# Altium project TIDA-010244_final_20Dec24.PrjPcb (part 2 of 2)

## Sheet TIDA-010244_USB_and_Power.SchDoc
size 431 x 279 mm; Date: Not shown in title block; ApprovedBy: Not shown in title block; CheckedBy: Not shown in title block; Author: Not shown in title block; CompanyName: Not shown in title block; Engineer: Not shown in title block; Organization: Not shown in title block; Address1: Not shown in title block; Address2: Not shown in title block; Address3: Not shown in title block; Address4: Not shown in title block; DocumentNumber: 6; Revision: Use project parameter SCH_Rev; SheetNumber: 5; SheetTotal: 9; PageSetup: Record=PageOptions¦CenterHorizontal=True¦CenterVertical=True¦PrintScale=1.00¦XCorrection=1.00¦YCorrection=1.00¦PrintKind=0¦BorderSize=5000000¦LeftOffset=0¦BottomOffset=0¦Orientation=2¦PaperLength=1000¦PaperWidth=1000¦Scale=100¦PaperSource=15¦PrintQuality=600¦MediaType=1¦DitherType=10¦PaperKind=Letter¦PrintScaleMode=1
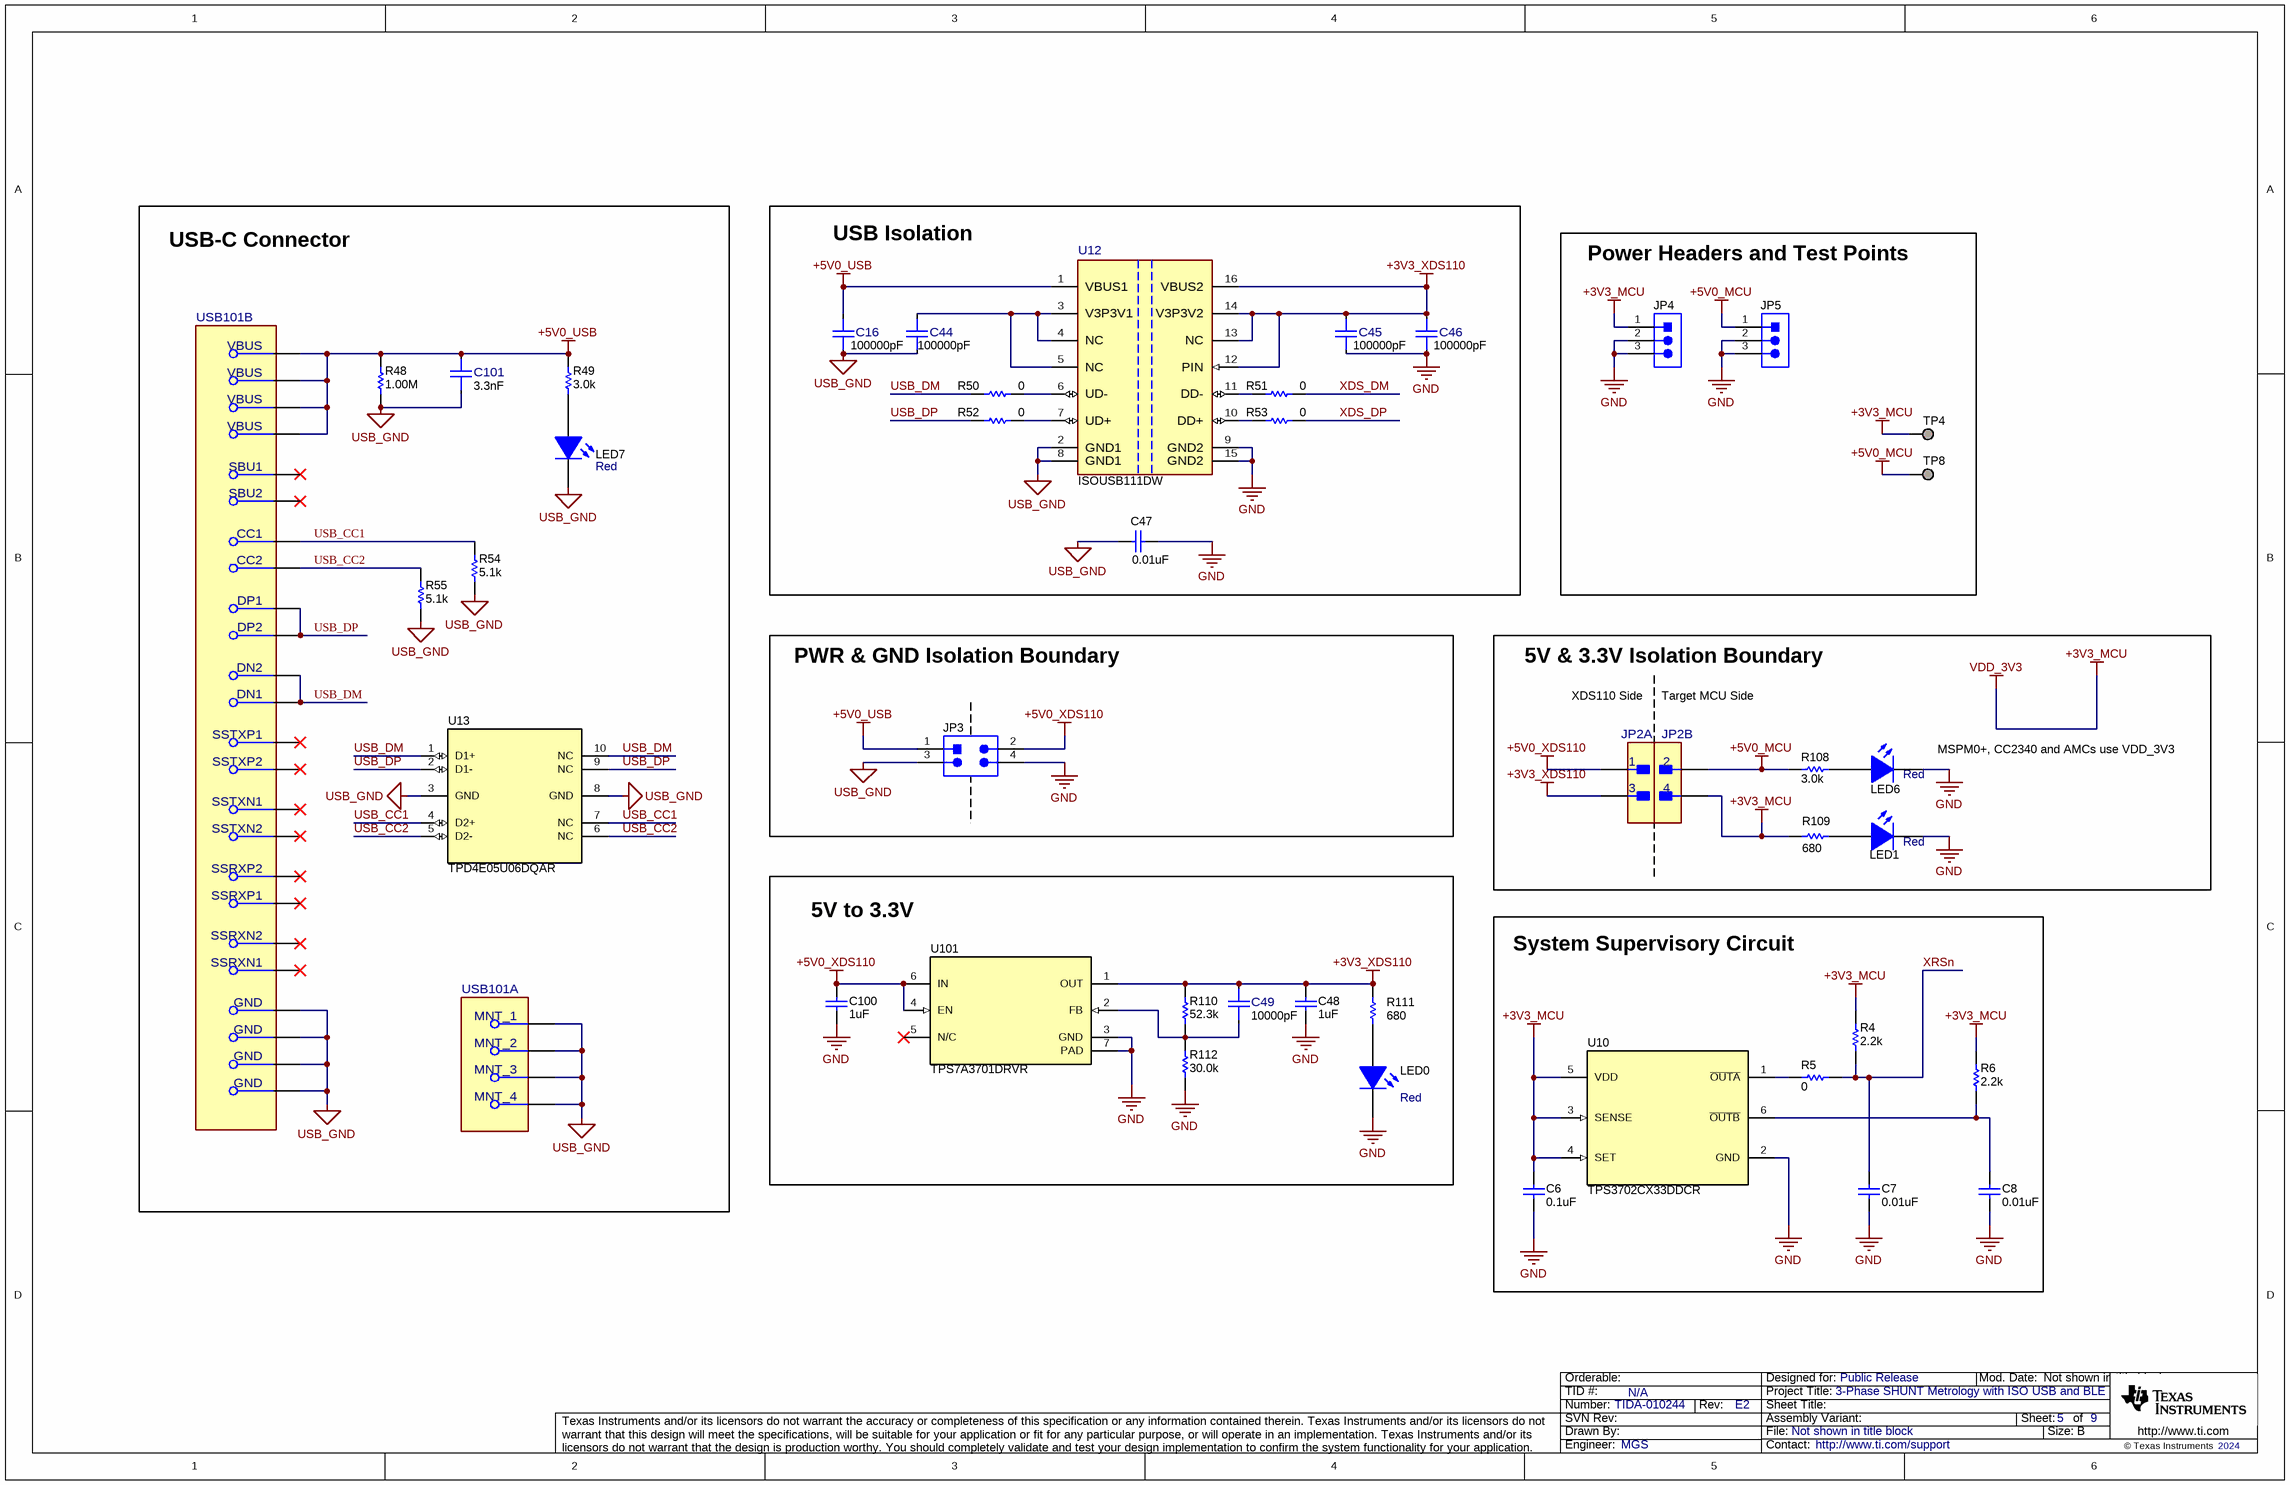
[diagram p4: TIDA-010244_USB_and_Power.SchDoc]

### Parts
C6  ValueDisplayed: 0.1uF  [0402]  (hidden comment: GRM155R71A104KA01D)
C7  ValueDisplayed: 0.01uF  [0402]  (hidden comment: GRM155R71E103KA01D)
C8  ValueDisplayed: 0.01uF  [0402]  (hidden comment: GRM155R71E103KA01D)
C16  ValueDisplayed: 100000pF  [FP-885012205018_0402-MFG]  (hidden comment: 885012205018)
C44  ValueDisplayed: 100000pF  [FP-885012205018_0402-MFG]  (hidden comment: 885012205018)
C45  ValueDisplayed: 100000pF  [FP-885012205018_0402-MFG]  (hidden comment: 885012205018)
C46  ValueDisplayed: 100000pF  [FP-885012205018_0402-MFG]  (hidden comment: 885012205018)
C47  ValueDisplayed: 0.01uF  [1812]  (hidden comment: 1812SC103KAT1A)
C48  ValueDisplayed: 1uF  [0402]  (hidden comment: 885012105012)
C49  ValueDisplayed: 10000pF  [FP-885012205050_0402-MFG]  (hidden comment: 885012205050)
C100  ValueDisplayed: 1uF  [0402]  (hidden comment: 885012105012)
C101  ValueDisplayed: 3.3nF  [FP-885012205064_0402-MFG]  (hidden comment: 885012205064)
JP2  61300421121  [FP-61300421121_HDR4-MFG]  (value not drawn)  (parts A,B of 2)
JP3  TSM-102-01-L-DV  [Samtec_TSM-102-01-x-DV]  (value not drawn)
JP4  61300311121  [WURTH_61300311121]  (value not drawn)
JP5  61300311121  [WURTH_61300311121]  (value not drawn)
LED0  value Red  [WL-SMCW_RED_0805]  (hidden comment: 150080SS75000)
LED1  value Red  [WL-SMCW_RED_0805]  (hidden comment: 150080SS75000)
LED6  value Red  [WL-SMCW_RED_0805]  (hidden comment: 150080SS75000)
LED7  value Red  [WL-SMCW_RED_0805]  (hidden comment: 150080SS75000)
R4  ValueDisplayed: 2.2k  [0402]  (hidden comment: CRCW04022K20JNED)
R5  ValueDisplayed: 0  [0402]  (hidden comment: CRCW04020000Z0ED)
R6  ValueDisplayed: 2.2k  [0603]  (hidden comment: CRCW06032K20JNEA)
R48  ValueDisplayed: 1.00M  [0402]  (hidden comment: CRCW04021M00FKED)
R49  ValueDisplayed: 3.0k  [0603]  (hidden comment: RC0603JR-073KL)
R50  ValueDisplayed: 0  [0402]  (hidden comment: RC0402JR-070RL)
R51  ValueDisplayed: 0  [0402]  (hidden comment: RC0402JR-070RL)
R52  ValueDisplayed: 0  [0402]  (hidden comment: RC0402JR-070RL)
R53  ValueDisplayed: 0  [0402]  (hidden comment: RC0402JR-070RL)
R54  ValueDisplayed: 5.1k  [0603]  (hidden comment: RC0603JR-075K1L)
R55  ValueDisplayed: 5.1k  [0603]  (hidden comment: RC0603JR-075K1L)
R108  ValueDisplayed: 3.0k  [0603]  (hidden comment: RC0603JR-073KL)
R109  ValueDisplayed: 680  [0402]  (hidden comment: CRCW0402680RJNED)
R110  ValueDisplayed: 52.3k  [0402]  (hidden comment: CRCW040252K3FKED)
R111  ValueDisplayed: 680  [0402]  (hidden comment: CRCW0402680RJNED)
R112  ValueDisplayed: 30.0k  [0402]  (hidden comment: CRCW040230K0FKED)
TP4  TESTPOINT  [TP_50MIL-25MILHOLE]  (value not drawn)  (no BOM)
TP8  TESTPOINT  [TP_50MIL-25MILHOLE]  (value not drawn)  (no BOM)
U10  TPS3702CX33DDCR  [DDC0006A_N]
U12  ISOUSB111DW  [DW0016B-MFG]
U13  TPD4E05U06DQAR  [DQA0010A]
U101  TPS7A3701DRVR  [DRV0006A]
USB101  MUP-U22001  [FP-MUP-U22001_CONN_USB_8MM94_8MM0-MFG]  (value not drawn)  (parts A,B of 2)

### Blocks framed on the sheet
USB-C Connector: C101 LED7 R48 R49 R54 R55 U13 USB101
USB Isolation: C16 C44-C47 R50-R53 U12
Power Headers and Test Points: JP4 JP5 TP4 TP8
PWR & GND Isolation Boundary: JP3
5V & 3.3V Isolation Boundary: JP2 LED1 LED6 R108 R109
5V to 3.3V: C48 C49 C100 LED0 R110-R112 U101
System Supervisory Circuit: C6-C8 R4-R6 U10

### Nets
+3V3_XDS110: C45.2 C46.2 C48.1 C49.2 JP2.3 R110.2 R111.2 U12.12(PIN) U12.13(NC) U12.14(V3P3V2) U12.16(VBUS2) U101.1(OUT)
+5V0_MCU: JP2.2 JP5.1 R108.2 TP8.1
+5V0_USB: C16.2 C101.2 JP3.1 R48.2 R49.2 U12.1(VBUS1) USB101.A4(VBUS) USB101.A9(VBUS) USB101.B4(VBUS) USB101.B9(VBUS)
+5V0_XDS110: C100.1 JP2.1 JP3.2 U101.4(EN) U101.6(IN)
GND: C6.1 C7.2 C8.2 C45.1 C46.1 C47.1 C48.2 C100.2 JP3.4 JP4.2 JP4.3 JP5.2 JP5.3 LED0.1(K) LED1.1(K) LED6.1(K) R112.1 U10.2(GND) U12.9(GND2) U12.15(GND2) U101.3(GND) U101.7(PAD)
USB_GND: C16.1 C44.1 C47.2 C101.1 JP3.3 LED7.1(K) R48.1 R54.1 R55.1 U12.2(GND1) U12.8(GND1) U13.3(GND) U13.8(GND) USB101.1(MNT_1) USB101.2(MNT_2) USB101.3(MNT_3) USB101.4(MNT_4) USB101.A1(GND) USB101.A12(GND) USB101.B1(GND) USB101.B12(GND)
VDD_3V3: C6.2 JP2.4 JP4.1 R4.2 R6.2 R109.2 TP4.1 U10.3(SENSE) U10.4(SET) U10.5(VDD)  [also labelled +3V3_MCU]
USB_CC1: R54.2 U13.4(D2+) U13.7(NC) USB101.A5(CC1)
USB_CC2: R55.2 U13.5(D2-) U13.6(NC) USB101.B5(CC2)
USB_DM: R50.1 U13.1(D1+) U13.10(NC) USB101.A7(DN1) USB101.B7(DN2)
USB_DP: R52.1 U13.2(D1-) U13.9(NC) USB101.A6(DP1) USB101.B6(DP2)
XDS_DM: R51.2
XDS_DP: R53.2
XRSn: C7.1 R4.1 R5.2
NetC8_1: C8.1 R6.1 U10.6(~{OUTB})
NetC44_2: C44.2 U12.3(V3P3V1) U12.4(NC) U12.5(NC)
NetC49_1: C49.1 R110.1 R112.2 U101.2(FB)
NetLED0_2: LED0.2(A) R111.1
NetLED1_2: LED1.2(A) R109.1
NetLED6_2: LED6.2(A) R108.1
NetLED7_2: LED7.2(A) R49.1
NetR5_1: R5.1 U10.1(~{OUTA})
NetR50_2: R50.2 U12.6(UD-)
NetR51_1: R51.1 U12.11(DD-)
NetR52_2: R52.2 U12.7(UD+)
NetR53_1: R53.1 U12.10(DD+)

Not connected (* = marked no-connect by the designer): U101 5(N/C)*; USB101 A2(SSTXP1)* A3(SSTXN1)* A8(SBU1)* A10(SSRXN2)* A11(SSRXP2)* B2(SSTXP2)* B3(SSTXN2)* B8(SBU2)* B10(SSRXN1)* B11(SSRXP1)*

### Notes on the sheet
- XDS110 Side
- Target MCU Side
- MSPM0+, CC2340 and AMCs use VDD_3V3

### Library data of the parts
C6 = CMP-0006629-2: CAP, CERM, 0.1 uF, 10 V, +/- 10%, X7R, 0402; Manufacturer: MuRata; Polarized: N; Value: 0.1uF; U/M: EA; Cap_F: 100nF; Value1: Unknown; VDC_V: 10V; TaMin_C: -55°C; TaMax_C: 125°C; SizeArea_mm2: 0.5; SizeAreaWB_mm2: 3; SizeX_mm: 1; SizeZ_mm: 0.6; AEC Category: Q200
C7 C8 = CMP-0006658-2: CAP, CERM, 0.01 uF, 25 V, +/- 10%, X7R, 0402; Manufacturer: MuRata; Polarized: N; Value: 0.01uF; U/M: EA; Cap_F: 10nF; Value1: Unknown; VDC_V: 25V; TaMin_C: -55°C; TaMax_C: 125°C; SizeArea_mm2: 0.5; SizeAreaWB_mm2: 3; SizeX_mm: 1; SizeZ_mm: 0.6; AEC Category: Q200
C16 C44-C46 = CMP-0090362-1: 0.1µF ±10% 10V Ceramic Capacitor X7R 0402 (1005 Metric); Manufacturer: Wurth Electronics; AEC Qualified: No; Value: 100nF; SizeZ_mm: 0.55mm; TempCo: 15%
C47 = CMP-0009297-2: CAP, CERM, 0.01 uF, 1500 V, +/- 10%, X7R, 1812; Manufacturer: AVX; TaMin_C: -55°C; ESR_ohm: 0.05; Polarized: N; SizeAreaWB_mm2: 23.1; Value1: 0.05 ohm; U/M: EA; Value: 0.01uF; TaMax_C: 125°C; SizeZ_mm: 1.35; SizeX_mm: 4.5; SizeY_mm: 3.2; Value2: 1500V; SizeArea_mm2: 14.4; Cap_F: 10nF; VDC_V: 1.5kV; AEC Category: Q200
C48 C100 = CMP-0064924-2: CAP, CERM, 1 uF, 10 V,+/- 20%, X5R, 0402; Manufacturer: Wurth Elektronik; Polarized: N; Value: 1uF; U/M: EA; Cap_F: 1µF; Value1: Unknown; VDC_V: 10V; TaMin_C: -55°C; TaMax_C: 85°C; SizeArea_mm2: 0.5; SizeAreaWB_mm2: 3; SizeX_mm: 1; SizeZ_mm: 0.6; AEC Category: Q200
C49 = CMP-0090363-1: 10000pF ±10% 25V Ceramic Capacitor X7R 0402 (1005 Metric); Manufacturer: Wurth Electronics; SizeZ_mm: 0.55mm; Cap_F: 10nF; AEC Qualified: No; Value: 10nF; TempCo: 15%
C101 = CMP-0092424-1: Cap Cer 3300pF 50V X7R 0402; Manufacturer: Wurth Electronics; TempCo: 15%; AEC Qualified: No; Value: 3.3nF; SizeZ_mm: 0.55mm; Tolerance_%: 10%
JP2 = CMP-0092422-1: THT Vertical Pin Header WR-PHD, Pitch 2.54 mm, Dual Row, 4 pins; Manufacturer: Wurth Electronics; DUT-Pitch_mm: 2.54mm; SizeZ_mm: 8.89mm; Voltage_V: 250V; Conn Gender: Male; AEC Qualified: No; Row_Count: 2; ContactFinish: Gold; Conn Orientation: Straight; Current_A: 3A
JP3 = CMP-0055559-1: Header, 2.54mm, 2x2, Gold, SMT; Manufacturer: Samtec; CNHeader: TRUE; Shrouded: N; Gender: Male; Cert_CSA: Y; Voltage_V: 475V; Row_Count: 2; Pitch_mm: 2.54; CT: FALSE
JP4 JP5 = CMP-0054796-1: Header, 2.54 mm, 3x1, Gold, TH; Manufacturer: Wurth Elektronik; Green_Lifecycle: Active; Green_REACh: Passed; CNHeader: TRUE; CT: FALSE
LED0 LED1 LED6 LED7 = CMP-0002951-3: LED, Red, SMD; Manufacturer: Wurth Elektronik; Type: AlInGaP; Vf_V: 1.9V; Io_A: 30mA; Vr_V: 5V; Ir_A: 25µA; Tjmax_C: 85°C; Power_TotalModule: 72mW; Value1: 0.072W; Angle: 140
R4 = CMP-0026890-5: RES, 2.2 k, 5%, 0.063 W, AEC-Q200 Grade 0, 0402; Manufacturer: Vishay-Dale; Value: 2.2k; Value_Code: 2k20; Power_W: 63mW; Value2: 0.063W; VDC_V: 50V; TempCo: 200 ppm/C; SizeArea_mm2: 0.5; SizeX_mm: 1; SizeZ_mm: 0.6; EIA_Code: E24; AEC Category: Q200; AEC Qualified: Y; AEC Grade: 0
R5 = CMP-0026822-3: RES, 0, 5%, 0.063 W, AEC-Q200 Grade 0, 0402; Manufacturer: Vishay-Dale; Value: 0; Value_Code: 0000; Power_W: 63mW; Value2: 0.063W; VDC_V: 50V; TempCo: 200 ppm/C; SizeArea_mm2: 0.5; SizeX_mm: 1; SizeZ_mm: 0.6; EIA_Code: E24; AEC Category: Q200; AEC Qualified: Y
R6 = CMP-0025769-4: RES, 2.2 k, 5%, 0.1 W, AEC-Q200 Grade 0, 0603; Manufacturer: Vishay-Dale; Value: 2.2k; Value_Code: 2k20; Power_W: 100mW; Value2: 0.1W; VDC_V: 75V; TempCo: 200 ppm/C; SizeArea_mm2: 1.28; SizeX_mm: 1.6; SizeY_mm: 0.8; SizeZ_mm: 1; EIA_Code: E24; AEC Category: Q200; AEC Qualified: Y; AEC Grade: 0
R48 = CMP-0026100-2: RES, 1.00 M, 1%, 0.063 W, AEC-Q200 Grade 0, 0402; Manufacturer: Vishay-Dale; Value: 1.00Meg; Res_ohm: 1M; Value_Code: 1M00; Power_W: 63mW; Value2: 0.063W; VDC_V: 50V; TempCo: 100 ppm/C; SizeArea_mm2: 0.5; SizeX_mm: 1; SizeZ_mm: 0.6; EIA_Code: E96; AEC Category: Q200; AEC Qualified: Y; AEC Grade: 0
R49 R108 = CMP-0025921-5: RES, 3.0 k, 5%, 0.1 W, 0603; Manufacturer: Yageo; Power_W: 100mW; TempCo: 100 ppm/C; Value_Code: 3k00; Value: 3.0k; EIA_Code: E24; Res_ohm: 3k; SizeX_mm: 1.6; SizeY_mm: 0.8; SizeZ_mm: 1; Value2: 0.1W; SizeArea_mm2: 1.28; AEC Qualified: N; VDC_V: 75V; AEC Category: Q200; SizeAreaWB_mm2: 4.68
R50-R53 = CMP-0027004-2: RES, 0, 5%, 0.063 W, 0402; Manufacturer: Yageo America; Power_W: 63mW; TempCo: 200 ppm/C; Value_Code: 0000; U/M: EA; Value: 0; EIA_Code: E24; SizeX_mm: 1; SizeY_mm: 0.5; SizeZ_mm: 0.6; Value2: 0.063W; VDC_V: 50V; AEC Category: Q200
R54 R55 = CMP-0025932-5: RES, 5.1 k, 5%, 0.1 W, 0603; Manufacturer: Yageo; Power_W: 100mW; TempCo: 100 ppm/C; Value_Code: 5k10; Value: 5.1k; EIA_Code: E24; SizeX_mm: 1.6; SizeY_mm: 0.8; SizeZ_mm: 1; Value2: 0.1W; SizeArea_mm2: 1.28; AEC Qualified: N; VDC_V: 75V; AEC Category: Q200; SizeAreaWB_mm2: 4.68
R109 R111 = CMP-0026962-3: RES, 680, 5%, 0.063 W, AEC-Q200 Grade 0, 0402; Manufacturer: Vishay-Dale; Power_W: 63mW; TempCo: 200 ppm/C; Value_Code: 680R; Value: 680; EIA_Code: E24; SizeX_mm: 1; SizeY_mm: 0.5; SizeZ_mm: 0.6; Value2: 0.063W; AEC Qualified: Y; VDC_V: 50V; AEC Category: Q200; AEC Grade: 0
R110 = CMP-0026441-2: RES, 52.3 k, 1%, 0.063 W, AEC-Q200 Grade 0, 0402; Manufacturer: Vishay-Dale; Power_W: 63mW; TempCo: 100 ppm/C; Value_Code: 52k3; Value: 52.3k; EIA_Code: E96; SizeX_mm: 1; SizeY_mm: 0.5; SizeZ_mm: 0.6; Value2: 0.063W; AEC Qualified: Y; VDC_V: 50V; AEC Category: Q200; AEC Grade: 0
R112 = CMP-0078244-2: RES, 30.0 k, 1%, 0.063 W, AEC-Q200 Grade 0, 0402; Manufacturer: Vishay-Dale; Power_W: 63mW; Green_Lifecycle: Active; TempCo: 100 ppm/C; Value_Code: 30k0; Green_REACh: Passed; Value: 30.0k; Res_ohm: 30k; SizeX_mm: 1; SizeY_mm: 0.5; SizeZ_mm: 0.6; Value2: 0.063W; AEC Qualified: Y; VDC_V: 50V; AEC Grade: 0; AEC Category: Q200
TP4 TP8 = CMP-0078143-3: TEST POINT.  No entry in BOM.
U10 = CMP-0067340-2: High-Accuracy, Fixed-Threshold OV/UV Monitor, DDC0006A (SOT-23-T-6); Alternate PartNumber: TPS3702CX33DDCT; Manufacturer: Texas Instruments; SizeArea_mm2: 4.8675; SizeAreaWB_mm2: 10.4675; SizeX_mm: 1.65; SizeY_mm: 2.95; SizeZ_mm: 0.87; CompType: IC; U/M: EA
U12 = CMP-0091303-1: Full/Low Speed Isolated USB Repeater, SOIC16-Wide; Manufacturer: Texas Instruments; Number Of Ports: 1; Usb Standard: USB 2.0; Min Supply Voltage: 3V; Data Rate: 12Mbits/s; Max Supply Voltage: 5.5V; TaMin_C: -40°C; SizeZ_mm: 2.65mm; TaMax_C: +125°C; Nominal Supply Current: 9-9.5mA; TJmax_C: +150°C; Standoff Height: 0.1mm; AEC Qualified: No
U13 = CMP-0073613-3: 4-Channel Ultra-Low-Capacitance IEC ESD Protection Diode, DQA0010A (USON-10); Alternate Manufacturer: Texas Instruments; Green_Lifecycle: Active; SizeAreaWB_mm2: 7.0; Green_REACh: Passed; SizeZ_mm: 0.55; SizeX_mm: 1.0; SizeY_mm: 2.5; CompType: IC; AEC Category: Q200; AEC Qualified: N
U101 = CMP-0066914-5: 1% High-Accuracy, 1-A, Low-Dropout Regulator with Reverse Current Protection, DRV0006A (WSON-6); Manufacturer: Texas Instruments; Alternate PartNumber: TPS7A3701DRVT; SizeX_mm: 2; CompType: IC; SizeZ_mm: 0.8; SizeArea_mm2: 4; SizeAreaWB_mm2: 9; U/M: EA
USB101 = CMP-0092137-1: Connector, USB Type-C 24 pin Mid Mount dual row Receptacle Surface Mount; Manufacturer: MUP; ContactFinish: Gold,Nickel; Usb Standard: OTHER; AEC Qualified: No; Conn Orientation: Horizontal; Shrouded: true; SizeZ_mm: 2.81mm; Is Female: yes; DUT-Pitch_mm: 0.5mm

## Sheet TIDA-010244_BLE_Wireless.SchDoc
size A4; Date: Not shown in title block; ApprovedBy: Not shown in title block; CheckedBy: Not shown in title block; Author: Not shown in title block; CompanyName: Not shown in title block; Engineer: Not shown in title block; Organization: Not shown in title block; Address1: Not shown in title block; Address2: Not shown in title block; Address3: Not shown in title block; Address4: Not shown in title block; DocumentNumber: 1; Revision: Use project parameter SCH_Rev; SheetNumber: 2; SheetTotal: 9; PageSetup: Record=PageOptions¦CenterHorizontal=True¦CenterVertical=True¦PrintScale=0.69¦XCorrection=1.00¦YCorrection=1.00¦PrintKind=0¦BorderSize=5000000¦LeftOffset=0¦BottomOffset=0¦Orientation=2¦PaperLength=1000¦PaperWidth=1000¦Scale=100¦PaperSource=15¦PrintQuality=600¦MediaType=1¦DitherType=10¦PaperKind=Letter¦PrintScaleMode=1
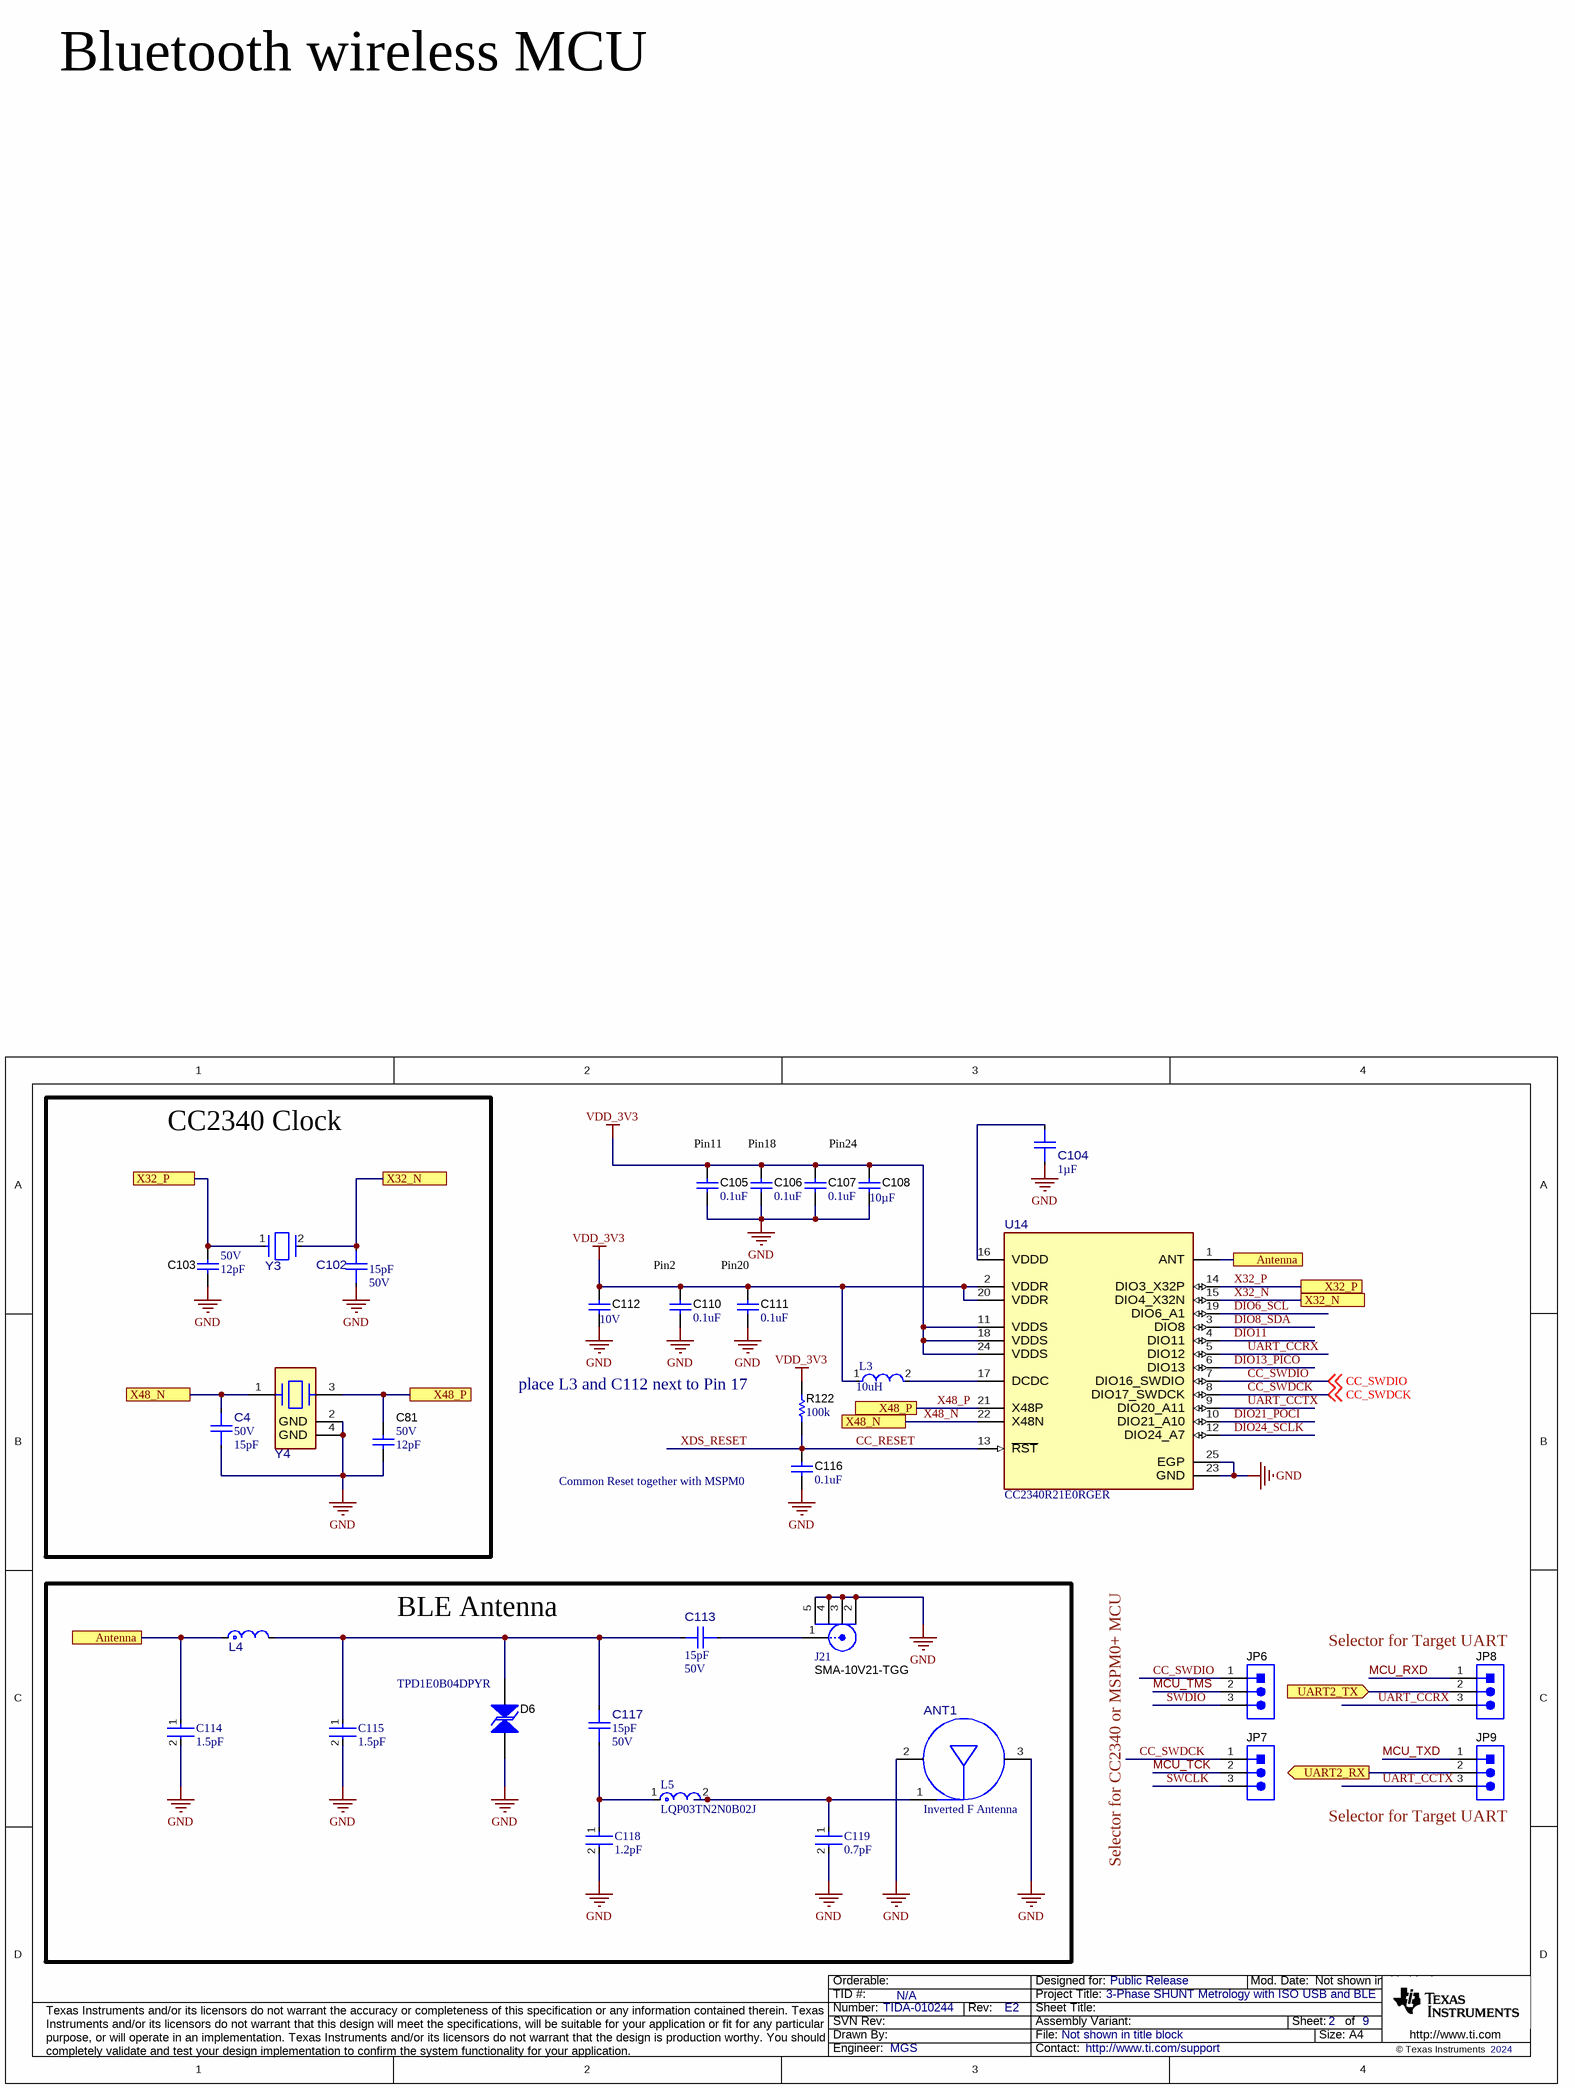
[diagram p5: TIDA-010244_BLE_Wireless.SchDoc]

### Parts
ANT1  Inverted F Antenna  [0-MFG]
C4  VDC_V: 50V  ValueDisplayed: 15pF  [FP-GRM0335C1H150GA01D_0201-IPC_B]  (hidden comment: GRM0335C1H150GA01D)
C81  VDC_V: 50V  ValueDisplayed: 12pF  [0201]  (hidden comment: GRM0335C1H120JA01D)
C102  ValueDisplayed: 15pF  VDC_V: 50V  [FP-GRM0335C1H150GA01D_0201-IPC_B]  (hidden comment: GRM0335C1H150GA01D)
C103  VDC_V: 50V  ValueDisplayed: 12pF  [0201]  (hidden comment: GRM0335C1H120JA01D)
C104  Cap_F: 1µF  [FP-GRM155Z71A105KE01D_0402-MFG]  (hidden comment: GRM155Z71A105KE01D)
C105  value 0.1uF  [0201]  (hidden comment: GRM033C71A104KE14D)
C106  value 0.1uF  [0201]  (hidden comment: GRM033C71A104KE14D)
C107  value 0.1uF  [0201]  (hidden comment: GRM033C71A104KE14D)
C108  Cap_F: 10µF  [0603]  (hidden comment: GRM188Z71A106KA73D)
C110  value 0.1uF  [0201]  (hidden comment: GRM033C71A104KE14D)
C111  value 0.1uF  [0201]  (hidden comment: GRM033C71A104KE14D)
C112  VDC_V: 10V  [0603]  (hidden comment: GRM188Z71A106KA73D)
C113  ValueDisplayed: 15pF  VDC_V: 50V  [FP-885012005056_0402-MFG]  (hidden comment: 885012005056)
C114  1.5pF  [FP-GRM033-0_03-IPC_C]
C115  1.5pF  [FP-GRM033-0_03-IPC_C]
C116  value 0.1uF  [0201]  (hidden comment: GRM033C71A104KE14D)
C117  ValueDisplayed: 15pF  VDC_V: 50V  [FP-885012005056_0402-MFG]  (hidden comment: 885012005056)
C118  1.2pF  [FP-GRM033-0_03-IPC_C]
C119  0.7pF  [FP-GRM033-0_03-MFG]
D6  TPD1E0B04DPYR  [DPY0002A]
J21  SMA-10V21-TGG  [Hustsan_SMA-10V21-TGG]
JP6  61300311121  [WURTH_61300311121]  (value not drawn)
JP7  61300311121  [WURTH_61300311121]  (value not drawn)
JP8  61300311121  [WURTH_61300311121]  (value not drawn)
JP9  61300311121  [WURTH_61300311121]  (value not drawn)
L3  10uH  [FP-LQM18DN_70-IPC_B]
L4  LQP03TN2N8B02J  [FP-LQP03TN2N8B02J_0201 (0603)-MFG]  (value not drawn)
L5  LQP03TN2N0B02J  [FP-LQP03TG_02-IPC_B]
R122  ValueDisplayed: 100k  [0201]  (hidden comment: RC0201FR-7D100KL)
U14  CC2340R21E0RGER  [RGE0024B-MFG]
Y3  TZ3359DAAO73  [FP-TZ3359DAAO73_SMT2_1MM65_1MM05-MFG]  (value not drawn)
Y4  TZ3908AAAO43  [FP-TZ3908AAAO43_SMT4_2MM05_1MM65-MFG]  (value not drawn)

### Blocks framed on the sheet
CC2340 Clock: C4 C81 C102 C103 Y3 Y4
BLE Antenna: ANT1 C113-C115 C117-C119 D6 J21 L4 L5

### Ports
Antenna, UART2_RX (out), UART2_TX (in), X32_N, X32_P, X48_N, X48_P

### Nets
GND: ANT1.2(GND) ANT1.3(GND) C4.1 C81.2 C102.1 C103.2 C104.1 C105.1 C106.1 C107.1 C108.1 C110.1 C111.1 C112.2 C114.2 C115.2 C116.1 C118.2 C119.2 D6.1 J21.2 J21.3 J21.4 J21.5 U14.23(GND) U14.25(EGP) Y4.2(GND) Y4.4(GND)
VDD_3V3: C105.2 C106.2 C107.2 C108.2 C110.2 C111.2 C112.1 L3.1 R122.1 U14.2(VDDR) U14.11(VDDS) U14.18(VDDS) U14.20(VDDR) U14.24(VDDS)
Antenna: C114.1 L4.1 U14.1(ANT) ; port Antenna
CC_RESET: C116.2 R122.2 U14.13(~{RST})  [also labelled XDS_RESET]
CC_SWDCK: JP7.1 U14.8(DIO17_SWDCK) ; off-sheet CC_SWDCK
CC_SWDIO: JP6.1 U14.7(DIO16_SWDIO) ; off-sheet CC_SWDIO
DIO6_SCL: U14.19(DIO6_A1)
DIO8_SDA: U14.3(DIO8)
DIO11: U14.4(DIO11)
DIO13_PICO: U14.6(DIO13)
DIO21_POCI: U14.10(DIO21_A10)
DIO24_SCLK: U14.12(DIO24_A7)
MCU_RXD: JP8.1
MCU_TCK: JP7.2
MCU_TMS: JP6.2
MCU_TXD: JP9.1
SWCLK: JP7.3
SWDIO: JP6.3
UART_CCRX: JP8.3 U14.5(DIO12)  [project net HY_RX]
UART_CCTX: JP9.3 U14.9(DIO20_A11)  [project net HY_TX]
UART_RX_to_BLE: JP9.2 ; port UART2_RX
UART_TX_to_BLE: JP8.2 ; port UART2_TX
X32_N: C102.2 U14.15(DIO4_X32N) Y3.2 ; port X32_N
X32_P: C103.1 U14.14(DIO3_X32P) Y3.1 ; port X32_P
X48_N: C4.2 U14.22(X48N) Y4.1(1_IN/OUT) ; port X48_N
X48_P: C81.1 U14.21(X48P) Y4.3(2_IN/OUT) ; port X48_P
NetANT1_1: ANT1.1(Feed) C119.1 L5.2
NetC104_2: C104.2 U14.16(VDDD)
NetC113_1: C113.1 J21.1
NetC113_2: C113.2 C115.1 C117.2 D6.2 L4.2
NetC117_1: C117.1 C118.1 L5.1
NetL3_2: L3.2 U14.17(DCDC)

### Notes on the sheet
- Bluetooth wireless MCU
- (near C105) Pin11
- (near C106) Pin18
- Pin24
- (near C110) Pin2
- (near C111) Pin20
- (near R122) place L3 and C112 next to Pin 17
- Common Reset together with MSPM0
- (near JP8) Selector for Target UART
- (near JP9) Selector for Target UART
- Selector for CC2340 or MSPM0+ MCU

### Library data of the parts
ANT1 = CMP-0091830-1: 2.4-GHz Inverted F Antenna; Manufacturer: Texas Instruments; AEC Qualified: No; Number Of Bands: 1
C4 = CMP-0001348-1: Chip Multilayer Ceramic Capacitors for General Purpose, 0201, 15pF, C0G, 30ppm/°C, 2%, 50V; Manufacturer: Murata; SizeZ_mm: 0.33mm; AEC Qualified: No
C81 C103 = CMP-0009664-3: CAP, CERM, 12 pF, 50 V, +/- 5%, C0G/NP0, 0201; Manufacturer: MuRata; SizeZ_mm: 0.26; Value: 12pF; AEC Qualified: N; TaMin_C: -55°C; SizeAreaWB_mm2: 2.08; Value1: Unknown; U/M: EA; TaMax_C: 125°C; SizeY_mm: 0.3; SizeArea_mm2: 0.18; SizeX_mm: 0.6; AEC Category: Q200
C102 = CMP-0001348-1: Chip Multilayer Ceramic Capacitors for General Purpose, 0201, 15pF, C0G, 30ppm/°C, 2%, 50V; Manufacturer: Murata; AEC Qualified: No; SizeZ_mm: 0.33mm
C104 = CMP-0092999-1: Chip Multilayer Ceramic Capacitors for General Purpose, 0402, 1.0uF, X7R, 15%, 10%, 10V; Manufacturer: Murata; Value: 1µF; SizeZ_mm: 0.6mm; AEC Qualified: No
C105-C107 C110 C111 C116 = CMP-0064969-1: CAP, CERM, 0.1 uF, 10 V,+/- 10%, X7S, 0201; Manufacturer: MuRata; TaMin_C: -55°C; Polarized: N; SizeAreaWB_mm2: 2.08; Value1: Unknown; U/M: EA; TaMax_C: 125°C; SizeZ_mm: 0.26; SizeX_mm: 0.6; SizeY_mm: 0.3; Value2: 10V; SizeArea_mm2: 0.18; AEC Category: Q200; Cap_F: 100nF
C108 = CMP-0087107-2: Chip Multilayer Ceramic Capacitors for General Purpose; Manufacturer: Murata; TempCo: 15%; Tolerance_%: 10%; SizeZ_mm: 1mm; AEC Qualified: No; VDC_V: 10V
C112 = CMP-0087107-2: Chip Multilayer Ceramic Capacitors for General Purpose; Manufacturer: Murata; TempCo: 15%; Tolerance_%: 10%; SizeZ_mm: 1mm; AEC Qualified: No; Cap_F: 10µF
C113 C117 = CMP-0090358-1: 15pF ±5% 50V Ceramic Capacitor C0G, NP0 0402 (1005 Metric); Manufacturer: Wurth Electronics; AEC Qualified: No; SizeZ_mm: 0.55mm; TempCo: 30ppm/°C
C114 C115 = CMP-06035-002174-1: Chip Multilayer Ceramic Capacitors for General Purpose, 0201, 1.5pF, C0G, 30ppm/°C, 0.1pF, 50V
C118 = CMP-2010-01514-2: Chip Multilayer Ceramic Capacitors for General Purpose, 0201, 1.2pF, C0G, 30ppm/°C, 0.1pF, 50V
C119 = CMP-06035-002085-1: Chip Multilayer Ceramic Capacitors for General Purpose, 0201, 0.70pF, C0G, 30ppm/°C, 0.1pF, 50V
D6 = CMP-0073606-3: 1-Channel ESD Protection Diode for USB Type-C and Antenna Protection, DPY0002A (X1SON-2); Manufacturer: Texas Instruments; Alternate PartNumber: TPD1E0B04DPYT; CompType: IC; SizeX_mm: 1.0; SizeAreaWB_mm2: 3.2; AEC Category: Q200; SizeZ_mm: 0.45; Rating: Catalog; SizeArea_mm2: 0.6
J21 = CMP-0055832-1: Connector, SMA, Vertical, Gold, SMT; Manufacturer: Hus-Tsan Group Co., Ltd.; CT: TRUE; CNHeader: FALSE
JP6-JP9 = CMP-0054796-1: as JP4 on sheet TIDA-010244_USB_and_Power
L3 = CMP-06042-017052-1: Multilayer type Inductor for Power Lines 10uH ±20% @1MHz, 300mA, Max DCR 1.365Ω, SRF 32MHz
L4 = CMP-0001349-1: Film type RF Inductor 2.8nH ±0.1nH 500mA 0.2Ω 0201 (0603); Manufacturer: Murata; AEC Qualified: No; DCR_ohm: 0.2; SizeZ_mm: 0.33mm; Q Factor: 14; Self Resonant Frequency: 9.5GHz; Test Frequency: 500MHz
L5 = CMP-06042-009700-1: Film type RF Inductor 2nH ±0.1nH 600mA 0.15Ω 0201 (0603)
R122 = CMP-0027943-1: RES, 100 k, 1%, 0.05 W, 0201; Manufacturer: Yageo America; Power_W: 50mW; TempCo: 200 ppm/C; Value: 100k; EIA_Code: E96; SizeX_mm: 0.6; SizeY_mm: 0.3; SizeZ_mm: 0.26; Value2: 0.05W; SizeArea_mm2: 0.18; AEC Qualified: N; VDC_V: 25V; AEC Category: Q200; U/M: EA
U14 = CMP-0033813-1: SimpleLink™ Bluetooth ® 5.3 Low Energy Wireless MCU QFN24 48MHz Arm® Cortex®-M0+ 28KB RAM 256KB FLASH; Manufacturer: Texas Instruments; SizeZ_mm: 1mm; AEC Qualified: No; Core Architecture: ARM Cortex-M0+; Data Bus Width: 32bits; Interface: I2C,SPI,UART,IrDA; Max Supply Voltage: 3.8V; Memory Size: 256KBytes; Min Supply Voltage: 1.71V; Number Of A/D Converters: 1; Number Of Adc Channels: 4; Number Of I/Os: 12; Number Of Pwm Channels: 2; Ram Size: 28KBytes; Standoff Height: 0mm; TaMax_C: +125°C; TaMin_C: -40°C
Y3 = CMP-0001358-1: Crystal Unit 1.6x1.0 Tuning Fork 32.768KHz; Manufacturer: TAI-SAW Technology; Frequency Stability: 380ppm; SizeZ_mm: 0.5mm; AEC Qualified: No; Frequency Tolerance: 20ppm; Load Capacitance: 7pF; Esr: 120k
Y4 = CMP-0001392-1: Crystal Unit SMD 2.0x1.6 48.0MHz; Manufacturer: TAI-SAW Thechnology; Frequency Stability: 30ppm; Frequency_Fixed: 48MHz; SizeZ_mm: 0.5mm; AEC Qualified: No; Frequency Tolerance: 5ppm; Load Capacitance: 7pF; Esr: 30

## Sheet TIDA-010244_XDS110_MCU.SchDoc
size 431 x 279 mm; Date: Not shown in title block; ApprovedBy: Not shown in title block; CheckedBy: Not shown in title block; Author: Not shown in title block; CompanyName: Not shown in title block; Engineer: Not shown in title block; Organization: Not shown in title block; Address1: Not shown in title block; Address2: Not shown in title block; Address3: Not shown in title block; Address4: Not shown in title block; DocumentNumber: 7; Revision: Use project parameter SCH_Rev; SheetNumber: 7; SheetTotal: 9; PageSetup: Record=PageOptions¦CenterHorizontal=True¦CenterVertical=True¦PrintScale=1.00¦XCorrection=1.00¦YCorrection=1.00¦PrintKind=0¦BorderSize=5000000¦LeftOffset=0¦BottomOffset=0¦Orientation=2¦PaperLength=1000¦PaperWidth=1000¦Scale=100¦PaperSource=15¦PrintQuality=600¦MediaType=1¦DitherType=10¦PaperKind=Letter¦PrintScaleMode=1
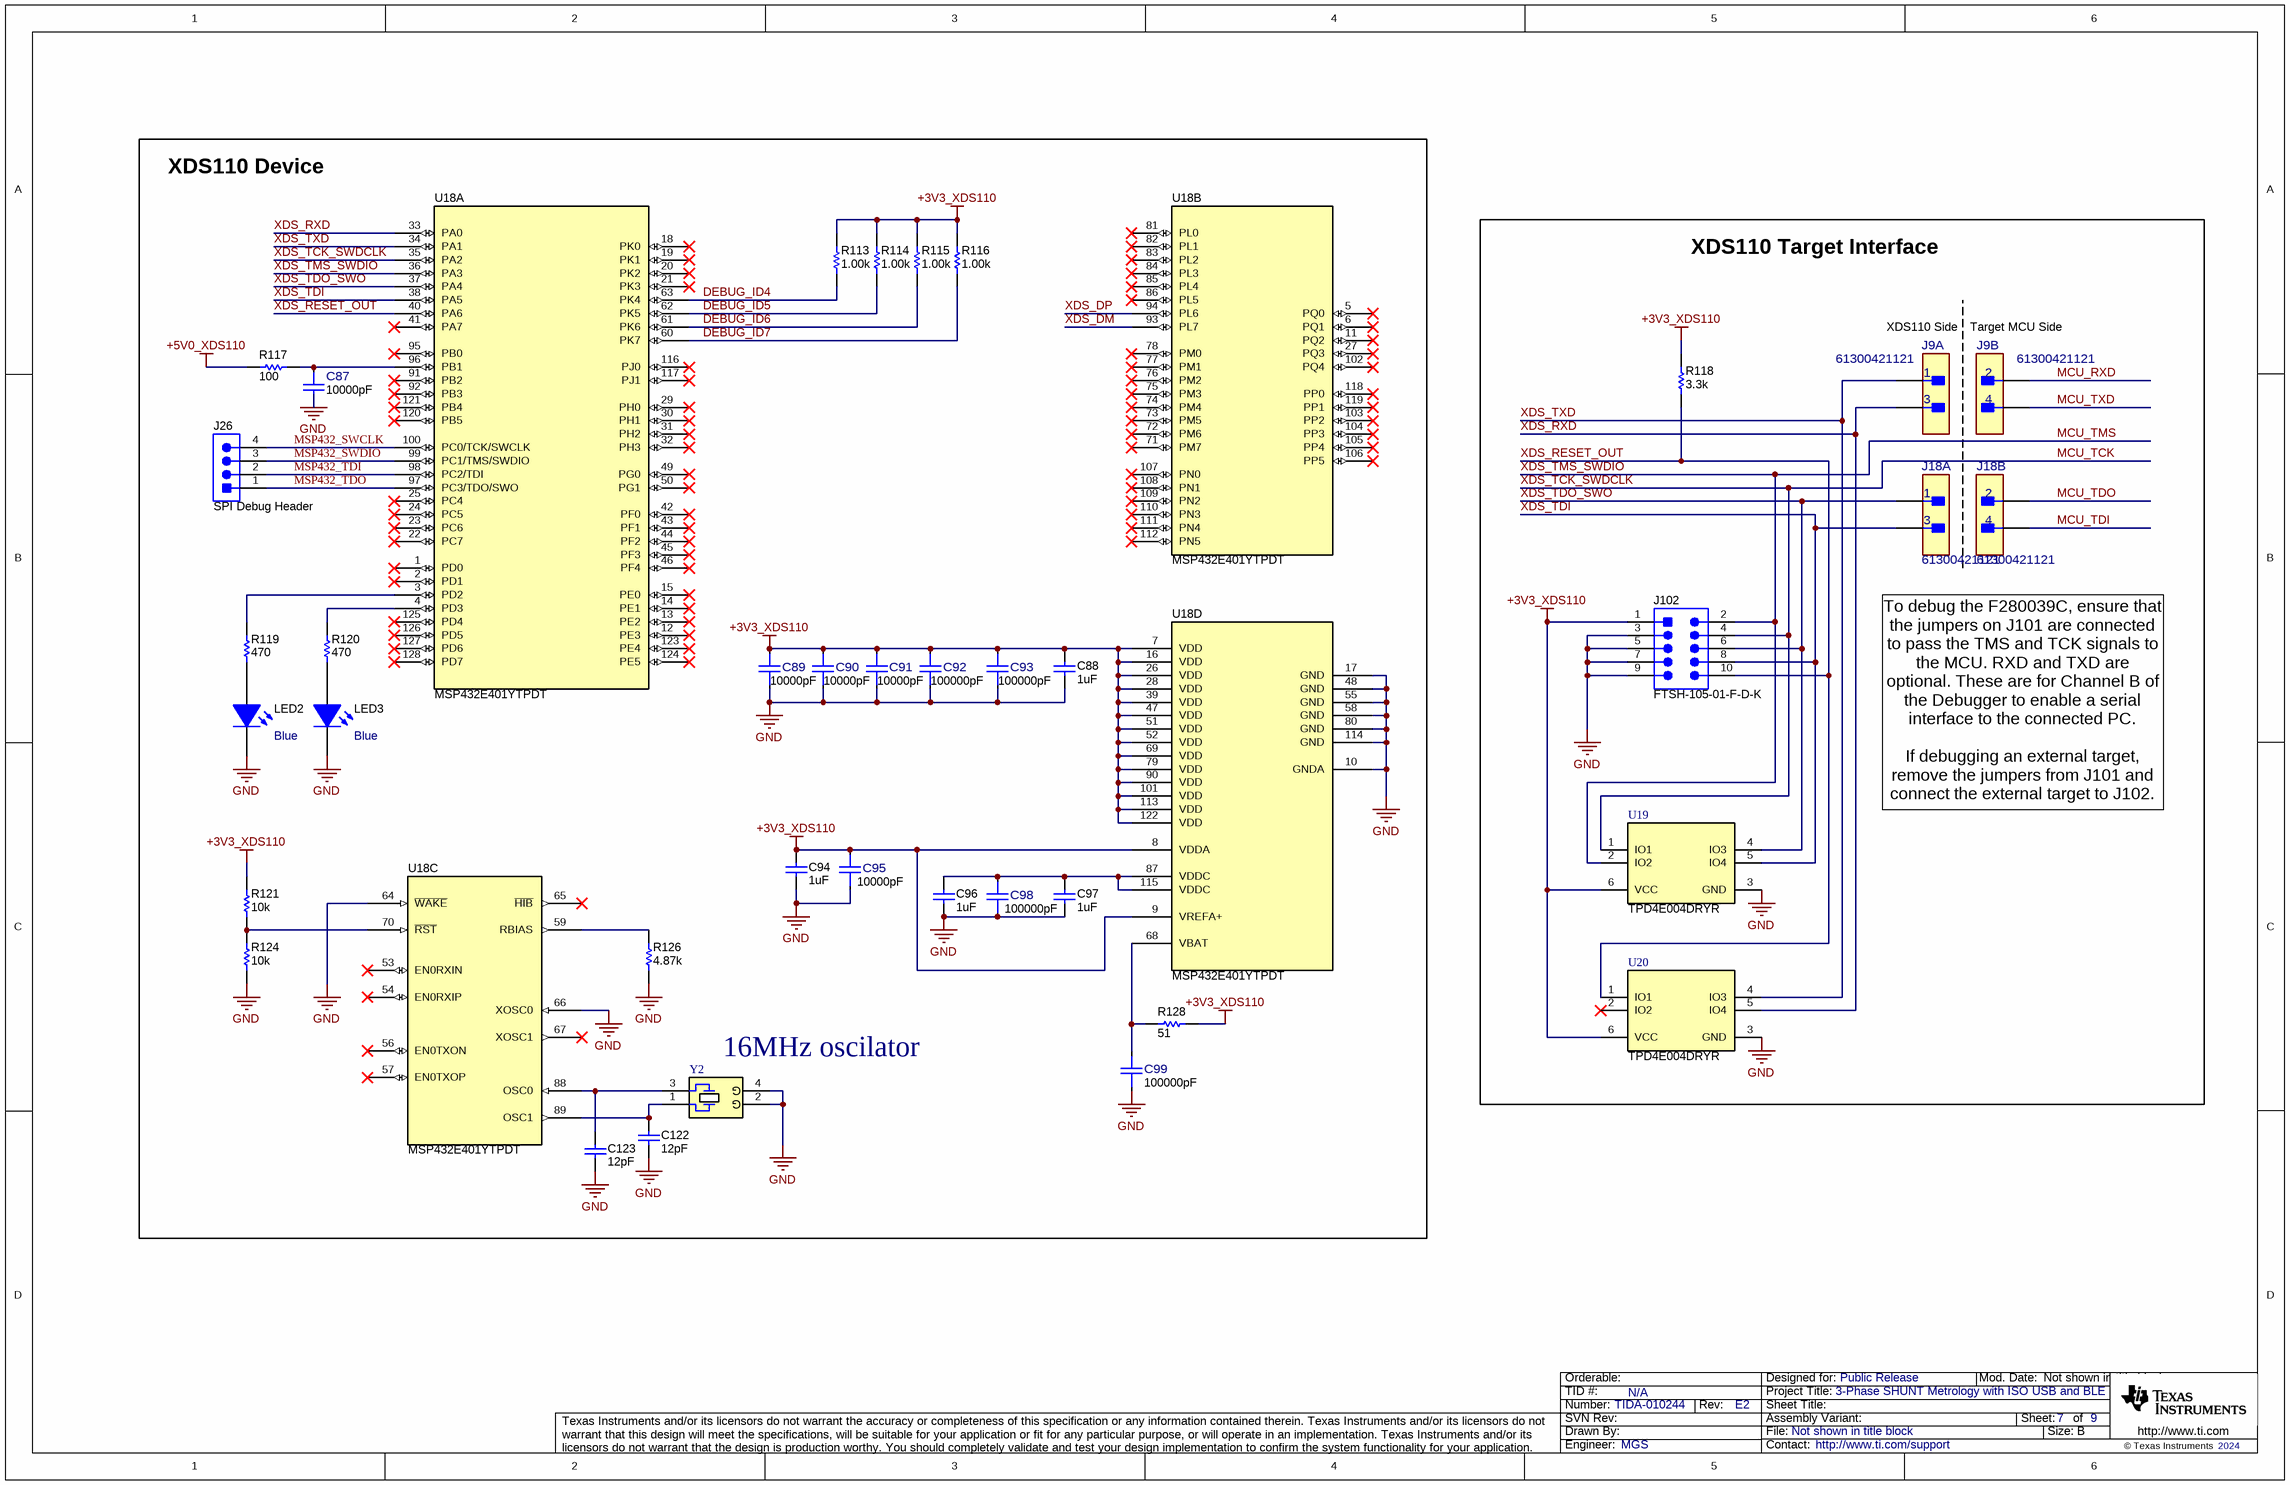
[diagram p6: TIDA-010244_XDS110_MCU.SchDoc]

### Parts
C87  ValueDisplayed: 10000pF  [FP-885012205050_0402-MFG]  (hidden comment: 885012205050)
C88  ValueDisplayed: 1uF  [0402]  (hidden comment: 885012105012)
C89  ValueDisplayed: 10000pF  [FP-885012205050_0402-MFG]  (hidden comment: 885012205050)
C90  ValueDisplayed: 10000pF  [FP-885012205050_0402-MFG]  (hidden comment: 885012205050)
C91  ValueDisplayed: 10000pF  [FP-885012205050_0402-MFG]  (hidden comment: 885012205050)
C92  ValueDisplayed: 100000pF  [FP-885012205018_0402-MFG]  (hidden comment: 885012205018)
C93  ValueDisplayed: 100000pF  [FP-885012205018_0402-MFG]  (hidden comment: 885012205018)
C94  ValueDisplayed: 1uF  [0402]  (hidden comment: 885012105012)
C95  ValueDisplayed: 10000pF  [FP-885012205050_0402-MFG]  (hidden comment: 885012205050)
C96  ValueDisplayed: 1uF  [0402]  (hidden comment: 885012105012)
C97  ValueDisplayed: 1uF  [0402]  (hidden comment: 885012105012)
C98  ValueDisplayed: 100000pF  [FP-885012205018_0402-MFG]  (hidden comment: 885012205018)
C99  ValueDisplayed: 100000pF  [FP-885012205018_0402-MFG]  (hidden comment: 885012205018)
C122  ValueDisplayed: 12pF  [0402]  (hidden comment: GRM1555C1H120JA01D)
C123  ValueDisplayed: 12pF  [0402]  (hidden comment: GRM1555C1H120JA01D)
J9  61300421121  [FP-61300421121_HDR4-MFG]  (parts A,B of 2)
J18  61300421121  [FP-61300421121_HDR4-MFG]  (parts A,B of 2)
J26  SPI Debug Header  [WURTH_61300411121]
J102  FTSH-105-01-F-D-K  [Samtec_FTSH-105-01-x-D-K]
LED2  value Blue  [LTST-C170TBKT_Blue]  (hidden comment: LTST-C170TBKT)
LED3  value Blue  [LTST-C170TBKT_Blue]  (hidden comment: LTST-C170TBKT)
R113  ValueDisplayed: 1.00k  [0402]  (hidden comment: CRCW04021K00FKED)
R114  ValueDisplayed: 1.00k  [0402]  (hidden comment: CRCW04021K00FKED)
R115  ValueDisplayed: 1.00k  [0402]  (hidden comment: CRCW04021K00FKED)
R116  ValueDisplayed: 1.00k  [0402]  (hidden comment: CRCW04021K00FKED)
R117  ValueDisplayed: 100  [0402]  (hidden comment: CRCW0402100RJNED)
R118  ValueDisplayed: 3.3k  [0402]  (hidden comment: CRCW04023K30JNED)
R119  ValueDisplayed: 470  [0402]  (hidden comment: RC0402FR-07470RL)
R120  ValueDisplayed: 470  [0402]  (hidden comment: RC0402FR-07470RL)
R121  ValueDisplayed: 10k  [0402]  (hidden comment: CRCW040210K0JNED)
R124  ValueDisplayed: 10k  [0402]  (hidden comment: CRCW040210K0JNED)
R126  ValueDisplayed: 4.87k  [0402]  (hidden comment: CRCW04024K87FKED)
R128  ValueDisplayed: 51  [0402]  (hidden comment: CRCW040251R0JNED)
U18  MSP432E401YTPDT  [PDT0128A]  (parts A,B,C,D of 4)
U19  TPD4E004DRYR  [DRY0006A]
U20  TPD4E004DRYR  [DRY0006A]
Y2  TSX-3225 16.0000MF20G-AC3  [EPSON_TSX-3225]  (value not drawn)

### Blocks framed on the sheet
16MHz oscilator: C87-C99 C122 C123 J26 LED2 LED3 R113-R117 R119-R121 R124 R126 R128 U18 Y2
XDS110 Target Interface: J9 J18 J102 R118 U19 U20

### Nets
+3V3_XDS110: C88.1 C89.2 C90.2 C91.2 C92.2 C93.2 C94.1 C95.2 J102.1 R113.2 R114.2 R115.2 R116.2 R118.2 R121.2 R128.2 U18.7(VDD) U18.8(VDDA) U18.9(VREFA+) U18.16(VDD) U18.26(VDD) U18.28(VDD) U18.39(VDD) U18.47(VDD) U18.51(VDD) U18.52(VDD) U18.69(VDD) U18.79(VDD) U18.90(VDD) U18.101(VDD) U18.113(VDD) U18.122(VDD) U19.6(VCC) U20.6(VCC)
+5V0_XDS110: R117.1
GND: C87.1 C88.2 C89.1 C90.1 C91.1 C92.1 C93.1 C94.2 C95.1 C96.2 C97.2 C98.1 C99.1 C122.2 C123.2 J102.3 J102.5 J102.7 J102.9 LED2.2(K) LED3.2(K) R124.1 R126.1 U18.10(GNDA) U18.17(GND) U18.48(GND) U18.55(GND) U18.58(GND) U18.64(~{WAKE}) U18.66(XOSC0) U18.80(GND) U18.114(GND) U19.3(GND) U20.3(GND) Y2.2(GND) Y2.4(GND)
DEBUG_ID4: R113.1 U18.63(PK4)
DEBUG_ID5: R114.1 U18.62(PK5)
DEBUG_ID6: R115.1 U18.61(PK6)
DEBUG_ID7: R116.1 U18.60(PK7)
MCU_RXD: J9.2
MCU_TCK: J102.4 U18.35(PA2) U19.1(IO1)  [also labelled XDS_TCK_SWDCLK]
MCU_TDI: J18.4
MCU_TDO: J18.2
MCU_TMS: J102.2 U18.36(PA3) U19.2(IO2)  [also labelled XDS_TMS_SWDIO]
MCU_TXD: J9.4
MSP432_SWCLK: J26.4 U18.100(PC0/TCK/SWCLK)
MSP432_SWDIO: J26.3 U18.99(PC1/TMS/SWDIO)
MSP432_TDI: J26.2 U18.98(PC2/TDI)
MSP432_TDO: J26.1 U18.97(PC3/TDO/SWO)
XDS_DM: U18.93(PL7)
XDS_DP: U18.94(PL6)
XDS_RESET_OUT: J102.10 R118.1 U18.40(PA6) U20.1(IO1)
XDS_RXD: J9.3 U18.33(PA0) U20.5(IO4)
XDS_TDI: J18.3 J102.8 U18.38(PA5) U19.5(IO4)
XDS_TDO_SWO: J18.1 J102.6 U18.37(PA4) U19.4(IO3)
XDS_TXD: J9.1 U18.34(PA1) U20.4(IO3)
NetC87_2: C87.2 R117.2 U18.96(PB1)
NetC96_1: C96.1 C97.1 C98.2 U18.87(VDDC) U18.115(VDDC)
NetC99_2: C99.2 R128.1 U18.68(VBAT)
NetC122_1: C122.1 U18.89(OSC1) Y2.1
NetC123_1: C123.1 U18.88(OSC0) Y2.3
NetLED2_1: LED2.1(A) R119.1
NetLED3_1: LED3.1(A) R120.1
NetR119_2: R119.2 U18.3(PD2)
NetR120_2: R120.2 U18.4(PD3)
NetR121_1: R121.1 R124.2 U18.70(~{RST})
NetR126_2: R126.2 U18.59(RBIAS)

Not connected (* = marked no-connect by the designer): U18 1(PD0)* 2(PD1)* 5(PQ0)* 6(PQ1)* 11(PQ2)* 12(PE3)* 13(PE2)* 14(PE1)* 15(PE0)* 18(PK0)* 19(PK1)* 20(PK2)* 21(PK3)* 22(PC7)* 23(PC6)* 24(PC5)* 25(PC4)* 27(PQ3)* 29(PH0)* 30(PH1)* 31(PH2)* 32(PH3)* 41(PA7)* 42(PF0)* 43(PF1)* 44(PF2)* 45(PF3)* 46(PF4)* 49(PG0)* 50(PG1)* 53(EN0RXIN)* 54(EN0RXIP)* 56(EN0TXON)* 57(EN0TXOP)* 65(~{HIB})* 67(XOSC1)* 71(PM7)* 72(PM6)* 73(PM5)* 74(PM4)* 75(PM3)* 76(PM2)* 77(PM1)* 78(PM0)* 81(PL0)* 82(PL1)* 83(PL2)* 84(PL3)* 85(PL4)* 86(PL5)* 91(PB2)* 92(PB3)* 95(PB0)* 102(PQ4)* 103(PP2)* 104(PP3)* 105(PP4)* 106(PP5)* 107(PN0)* 108(PN1)* 109(PN2)* 110(PN3)* 111(PN4)* 112(PN5)* 116(PJ0)* 117(PJ1)* 118(PP0)* 119(PP1)* 120(PB5)* 121(PB4)* 123(PE4)* 124(PE5)* 125(PD4)* 126(PD5)* 127(PD6)* 128(PD7)*; U20 2(IO2)*

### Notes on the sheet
- XDS110 Device
- (near J9) XDS110 Side
- (near J9) Target MCU Side
- To debug the F280039C, ensure that the jumpers on J101 are connected to pass the TMS and TCK signals to the MCU. RXD and TXD are optional. These are for Channel B of the Debugger to enable a serial interface to the connected PC.
  If debugging an external target, remove the jumpers from J101 and connect the external target to J102.

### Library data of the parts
C87 C89-C91 C95 = CMP-0090363-1: as C49 on sheet TIDA-010244_USB_and_Power
C88 C94 C96 C97 = CMP-0064924-2: as C48 on sheet TIDA-010244_USB_and_Power
C92 C93 C98 C99 = CMP-0090362-1: as C16 on sheet TIDA-010244_USB_and_Power
C122 C123 = CMP-0006415-2: CAP, CERM, 12 pF, 50 V, +/- 5%, C0G/NP0, 0402; Manufacturer: MuRata; TaMin_C: -55°C; Polarized: N; SizeAreaWB_mm2: 3; Value1: Unknown; U/M: EA; Value: 12pF; TaMax_C: 125°C; SizeZ_mm: 0.6; SizeX_mm: 1; SizeY_mm: 0.5; Value2: 50V; AEC Category: Q200
J9 J18 = CMP-0092422-1: as JP2 on sheet TIDA-010244_USB_and_Power
J26 = CMP-0054798-2: Header, 2.54 mm, 4x1, Gold, TH; Manufacturer: Wurth Elektronik; PartNumber: 61300411121; Pitch_mm: 2.54; Gender: Male; Row_Count: 1; Cert_UL: Y; Shrouded: N
J102 = CMP-0075533-1: Header, 1.27 mm, 5x2, Gold, TH; Manufacturer: Samtec; Pitch_mm: 1.27; Gender: Male; Green_REACh: Passed; CT: False; Shrouded: Y; Green_Lifecycle: Active; Row_Count: 2
LED2 LED3 = CMP-0002889-2: LED, Blue, SMD; Manufacturer: Lite-On; Type: AlInGaP; Vf_V: 3.3V; Io_A: 20mA; Value1: W
R113-R116 = CMP-0026071-3: RES, 1.00 k, 1%, 0.063 W, AEC-Q200 Grade 0, 0402; Manufacturer: Vishay-Dale; Power_W: 63mW; TempCo: 100 ppm/C; Value_Code: 1k00; Value: 1.00k; EIA_Code: E96; Res_ohm: 1k; SizeX_mm: 1; SizeY_mm: 0.5; SizeZ_mm: 0.6; Value2: 0.063W; AEC Qualified: Y; VDC_V: 50V; AEC Category: Q200; AEC Grade: 0
R117 = CMP-0026824-3: RES, 100, 5%, 0.063 W, AEC-Q200 Grade 0, 0402; Manufacturer: Vishay-Dale; Value: 100; Value_Code: 100R; Power_W: 63mW; Value2: 0.063W; VDC_V: 50V; TempCo: 200 ppm/C; SizeArea_mm2: 0.5; SizeX_mm: 1; SizeZ_mm: 0.6; EIA_Code: E24; AEC Category: Q200; AEC Qualified: Y; AEC Grade: 0
R118 = CMP-0026918-5: RES, 3.3 k, 5%, 0.063 W, AEC-Q200 Grade 0, 0402; Manufacturer: Vishay-Dale; Value: 3.3k; Value_Code: 3k30; Power_W: 63mW; Value2: 0.063W; VDC_V: 50V; TempCo: 200 ppm/C; SizeArea_mm2: 0.5; SizeX_mm: 1; SizeZ_mm: 0.6; EIA_Code: E24; AEC Category: Q200; AEC Qualified: Y; AEC Grade: 0
R119 R120 = CMP-0026736-1: RES, 470, 1%, 0.063 W, 0402; Manufacturer: Yageo America; Power_W: 63mW; TempCo: 100 ppm/C; Value_Code: 470R; U/M: EA; Value: 470; SizeX_mm: 1; SizeY_mm: 0.5; SizeZ_mm: 0.6; Value2: 0.063W; AEC Qualified: N; VDC_V: 50V; AEC Category: Q200
R121 R124 = CMP-0026825-5: RES, 10 k, 5%, 0.063 W, AEC-Q200 Grade 0, 0402; Manufacturer: Vishay-Dale; Value: 10k; Value_Code: 10k0; Power_W: 63mW; Value2: 0.063W; VDC_V: 50V; TempCo: 200 ppm/C; SizeArea_mm2: 0.5; SizeX_mm: 1; SizeZ_mm: 0.6; EIA_Code: E24; AEC Category: Q200; AEC Qualified: Y; AEC Grade: 0
R126 = CMP-0026413-2: RES, 4.87 k, 1%, 0.063 W, AEC-Q200 Grade 0, 0402; Manufacturer: Vishay-Dale; Value: 4.87k; Value_Code: 4k87; Power_W: 63mW; Value2: 0.063W; VDC_V: 50V; TempCo: 100 ppm/C; SizeArea_mm2: 0.5; SizeX_mm: 1; SizeZ_mm: 0.6; EIA_Code: E96; AEC Category: Q200; AEC Qualified: Y; AEC Grade: 0
R128 = CMP-0026946-3: RES, 51, 5%, 0.063 W, AEC-Q200 Grade 0, 0402; Manufacturer: Vishay-Dale; Value: 51; Value_Code: 51R0; Power_W: 63mW; Value2: 0.063W; VDC_V: 50V; TempCo: 200 ppm/C; SizeArea_mm2: 0.5; SizeX_mm: 1; SizeZ_mm: 0.6; EIA_Code: E24; AEC Category: Q200; AEC Qualified: Y; AEC Grade: 0
U18 = CMP-0077953-1: MSP432E401YTPDT, PDT0128A (TQFP-128); Alternate PartNumber: MSP432E401YTPDTR; Alternate Manufacturer: Texas Instruments; SizeAreaWB_mm2: 324; SizeZ_mm: 1.2; SizeX_mm: 16; SizeArea_mm2: 256; CompType: IC; AEC Qualified: N; AEC Category: Q200
U19 U20 = CMP-0043115-3: 4-Channel ESD Protection Array for High-Speed Data Interfaces, DRY0006A (USON-6); Manufacturer: Texas Instruments; IO Leakage Current(nA): 1; USB High Speed: TRUE; IO Capacitance(Typ)(pF): 1.6; Eco-Plan: Green (RoHS & no Sb/Br); IEC 61000-4-2 Contact(+/- kV): 8; Breakdown Voltage(Min)(V): 6; IEC 61000-4-2 Air-Gap(+/- kV): 12; AEC Category: Q200; AEC Qualified: N; CompType: IC; SizeAreaWB_mm2: 4.9; SizeArea_mm2: 1.45; SizeX_mm: 1.0; SizeZ_mm: 0.6; Rating: Catalog
Y2 = CMP-0004609-3: Crystal, 16 MHz, 9 pF, SMD / Orderable part number X1E0000210116xx /; Manufacturer: Epson; PartNumber: TSX-3225 24.0000MF20G-AC3; TaMin_C: -40°C; Frequency Stability: +/-20ppm; Frequency_Fixed: 24MHz; TaMax_C: 85°C

## Sheet TIDA-010244_Neutral_3DHall_Rev2.SchDoc
size A4; Date: Not shown in title block; ApprovedBy: Not shown in title block; CheckedBy: Not shown in title block; Author: Not shown in title block; CompanyName: Not shown in title block; Engineer: Not shown in title block; Organization: Not shown in title block; Address1: Not shown in title block; Address2: Not shown in title block; Address3: Not shown in title block; Address4: Not shown in title block; DocumentNumber: 1; Revision: Use project parameter SCH_Rev; SheetNumber: 9; SheetTotal: 10; PageSetup: Record=PageOptions¦CenterHorizontal=True¦CenterVertical=True¦PrintScale=0.69¦XCorrection=1.00¦YCorrection=1.00¦PrintKind=0¦BorderSize=5000000¦LeftOffset=0¦BottomOffset=0¦Orientation=2¦PaperLength=1000¦PaperWidth=1000¦Scale=100¦PaperSource=15¦PrintQuality=600¦MediaType=1¦DitherType=10¦PaperKind=Letter¦PrintScaleMode=1
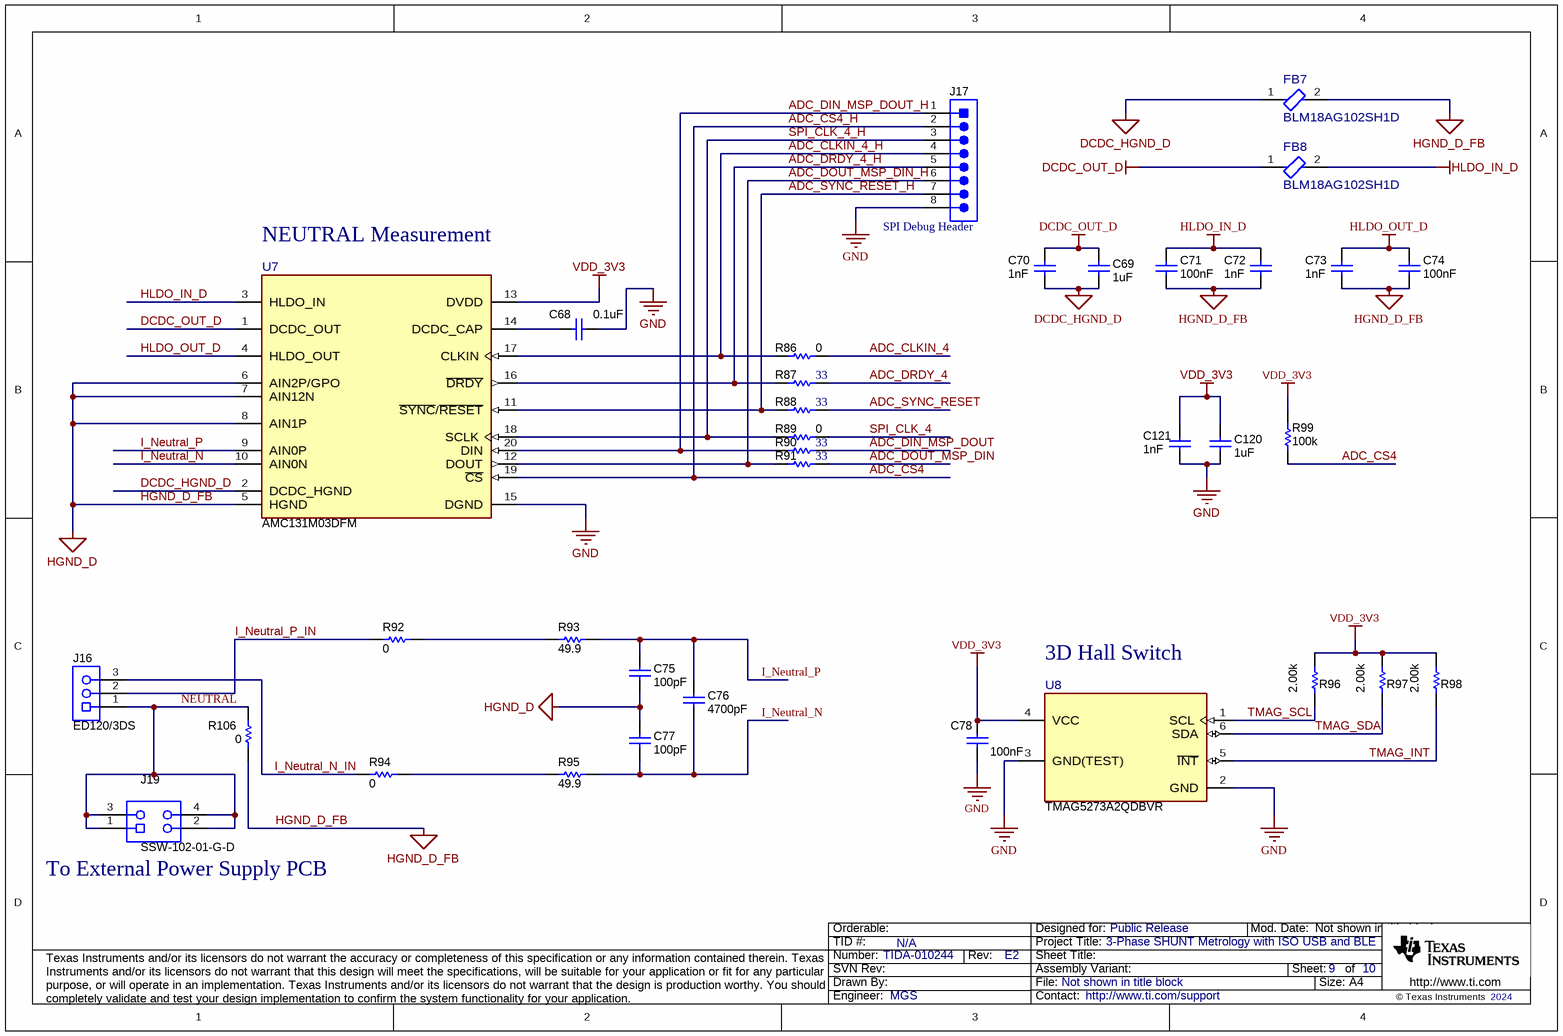
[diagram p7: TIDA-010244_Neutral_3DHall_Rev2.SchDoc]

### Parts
C68  value 0.1uF  [0603]  (hidden comment: C1608X7R1H104K080AA)
C69  ValueDisplayed: 1uF  [0603]  (hidden comment: C0603C105K3RACTU)
C70  Cap_F: 1nF  [0603]  (hidden comment: C0603C102K5RACTU)
C71  Cap_F: 100nF  [0603]  (hidden comment: C1608X7R1H104K080AA)
C72  Cap_F: 1nF  [0603]  (hidden comment: C0603C102K5RACTU)
C73  Cap_F: 1nF  [0603]  (hidden comment: C0603C102K5RACTU)
C74  Cap_F: 100nF  [0603]  (hidden comment: C1608X7R1H104K080AA)
C75  ValueDisplayed: 100pF  [0603]  (hidden comment: 885012006057)
C76  ValueDisplayed: 4700pF  [0603]  (hidden comment: C0603C472J1GAC7867)
C77  ValueDisplayed: 100pF  [0603]  (hidden comment: 885012006057)
C78  Cap_F: 100nF  [0603]  (hidden comment: C0603X104K3RACTU)
C120  ValueDisplayed: 1uF  [0603]  (hidden comment: C0603C105K3RACTU)
C121  Cap_F: 1nF  [0603]  (hidden comment: C0603C102K5RACTU)
FB7  BLM18AG102SH1D  [FP-BLM18AG102SH1D_0603-MFG]
FB8  BLM18AG102SH1D  [FP-BLM18AG102SH1D_0603-MFG]
J16  ED120/3DS  [On-Shore_ED120_3DS]
J17  800-10-008-10-001000  [Mill-Max_800-10-008-10-001000]  (value not drawn)
J19  SSW-102-01-G-D  [Samtec_SSW-102-01-x-D]
R86  ValueDisplayed: 0  [0603]  (hidden comment: ERJ-3GEY0R00V)
R87  ValueDisplayed: 33  [0603]  (hidden comment: CRCW060333R0JNEA)
R88  ValueDisplayed: 33  [0603]  (hidden comment: CRCW060333R0JNEA)
R89  ValueDisplayed: 0  [0603]  (hidden comment: ERJ-3GEY0R00V)
R90  ValueDisplayed: 33  [0603]  (hidden comment: CRCW060333R0JNEA)
R91  ValueDisplayed: 33  [0603]  (hidden comment: CRCW060333R0JNEA)
R92  ValueDisplayed: 0  [0603]  (hidden comment: RC0603JR-070RL)
R93  ValueDisplayed: 49.9  [0603]  (hidden comment: CRCW060349R9FKEA)
R94  ValueDisplayed: 0  [0603]  (hidden comment: RC0603JR-070RL)
R95  ValueDisplayed: 49.9  [0603]  (hidden comment: CRCW060349R9FKEA)
R96  ValueDisplayed: 2.00k  [0603]  (hidden comment: RT0603DRD072KL)
R97  ValueDisplayed: 2.00k  [0603]  (hidden comment: RT0603DRD072KL)
R98  ValueDisplayed: 2.00k  [0603]  (hidden comment: RT0603DRD072KL)
R99  ValueDisplayed: 100k  [0603]  (hidden comment: CRCW0603100KFKEA)
R106  ValueDisplayed: 0  [0603]  (hidden comment: RC0603JR-070RL)
U7  AMC131M03DFM  [DFM0020A-MFG]
U8  TMAG5273A2QDBVR  [DBV0006A-MFG]

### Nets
DCDC_HGND_D: C69.1 C70.2 FB7.1 U7.2(DCDC_HGND)
DCDC_OUT_D: C69.2 C70.1 FB8.1 U7.1(DCDC_OUT)
GND: C68.2 C78.2 C120.1 C121.2 J17.8 U7.15(DGND) U8.2(GND) U8.3(GND(TEST))
HGND_D_FB: C71.2 C72.2 C73.2 C74.2 C75.2 C77.1 FB7.2 R106.1 U7.5(HGND) U7.6(AIN2P/GPO) U7.7(AIN12N) U7.8(AIN1P)  [also labelled HGND_D]
HLDO_IN_D: C71.1 C72.1 FB8.2 U7.3(HLDO_IN)
HLDO_OUT_D: C73.1 C74.1 U7.4(HLDO_OUT)
VDD_3V3: C78.1 C120.2 C121.1 R96.2 R97.2 R98.2 R99.2 U7.13(DVDD) U8.4(VCC)
ADC_CLKIN_4: R86.2
ADC_CLKIN_4_H: J17.4 R86.1 U7.17(CLKIN)
ADC_CS4: J17.2 R99.1 U7.19(~{CS})  [also labelled ADC_CS4_H]
ADC_DIN_MSP_DOUT: R90.2
ADC_DIN_MSP_DOUT_H: J17.1 R90.1 U7.20(DIN)
ADC_DOUT_MSP_DIN: R91.2
ADC_DOUT_MSP_DIN_H: J17.6 R91.1 U7.12(DOUT)
ADC_DRDY_4: R87.2
ADC_DRDY_4_H: J17.5 R87.1 U7.16(~{DRDY})
ADC_SYNC_RESET: R88.2
ADC_SYNC_RESET_H: J17.7 R88.1 U7.11(~{SYNC}/~{RESET})
I_Neutral_N: C76.2 C77.2 R95.2 U7.10(AIN0N)
I_Neutral_N_IN: J16.3 R94.1
I_Neutral_P: C75.1 C76.1 R93.2 U7.9(AIN0P)
I_Neutral_P_IN: J16.2 R92.1
NEUTRAL: J16.1 J19.1 J19.2 J19.3 J19.4 R106.2
SPI_CLK_4: R89.2
SPI_CLK_4_H: J17.3 R89.1 U7.18(SCLK)
TMAG_INT: R98.1 U8.5(~{INT})
TMAG_SCL: R96.1 U8.1(SCL)
TMAG_SDA: R97.1 U8.6(SDA)
NetC68_1: C68.1 U7.14(DCDC_CAP)
NetR92_2: R92.2 R93.1
NetR94_2: R94.2 R95.1

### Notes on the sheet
- NEUTRAL Measurement
- (near J17) SPI Debug Header
- 3D Hall Switch
- (near J19) To External Power Supply PCB

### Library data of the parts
C68 = CMP-0007044-5: CAP, CERM, 0.1 uF, 50 V, +/- 10%, X7R, 0603; Manufacturer: TDK; TaMin_C: -55°C; ESR_ohm: 29.6m; Polarized: N; SizeAreaWB_mm2: 4.68; Value1: 0.0296 ohm; U/M: EA; TaMax_C: 125°C; SizeZ_mm: 1; SizeX_mm: 1.6; SizeY_mm: 0.8; Value2: 50V; SizeArea_mm2: 1.28; IRMS_A: 971.99mA; AEC Category: Q200
C69 C120 = CMP-0006867-4: CAP, CERM, 1 uF, 25 V, +/- 10%, X7R, 0603; Manufacturer: Kemet; TaMin_C: -55°C; Polarized: N; SizeAreaWB_mm2: 4.68; Value1: Unknown; U/M: EA; Value: 1uF; TaMax_C: 125°C; SizeZ_mm: 1; SizeX_mm: 1.6; SizeY_mm: 0.8; Value2: 25V; SizeArea_mm2: 1.28; CompType: Capacitor; Cap_F: 1µF; AEC Category: Q200
C70 C72 C73 C121 = CMP-0006847-4: CAP, CERM, 1000 pF, 50 V, +/- 10%, X7R, 0603; Manufacturer: Kemet; TaMin_C: -55°C; Polarized: N; SizeAreaWB_mm2: 4.68; Value1: Unknown; U/M: EA; Value: 1000pF; TaMax_C: 125°C; SizeZ_mm: 1; SizeX_mm: 1.6; SizeY_mm: 0.8; Value2: 50V; SizeArea_mm2: 1.28; AEC Category: Q200
C71 C74 = CMP-0007044-5: CAP, CERM, 0.1 uF, 50 V, +/- 10%, X7R, 0603; Manufacturer: TDK; TaMin_C: -55°C; ESR_ohm: 29.6m; Polarized: N; SizeAreaWB_mm2: 4.68; Value1: 0.0296 ohm; U/M: EA; Value: 0.1uF; TaMax_C: 125°C; SizeZ_mm: 1; SizeX_mm: 1.6; SizeY_mm: 0.8; Value2: 50V; SizeArea_mm2: 1.28; IRMS_A: 971.99mA; AEC Category: Q200
C75 C77 = CMP-0006822-4: CAP, CERM, 100 pF, 50 V, +/- 5%, C0G/NP0, 0603; Manufacturer: Wurth Elektronik; TaMin_C: -55°C; Polarized: N; SizeAreaWB_mm2: 4.68; Value1: Unknown; U/M: EA; Value: 100pF; TaMax_C: 125°C; SizeZ_mm: 1; SizeX_mm: 1.6; SizeY_mm: 0.8; Value2: 50V; SizeArea_mm2: 1.28; AEC Category: Q200
C76 = CMP-0006941-4: CAP, CERM, 4700 pF, 100 V, +/- 5%, C0G/NP0, 0603; Manufacturer: Kemet; TaMin_C: -55°C; Polarized: N; SizeAreaWB_mm2: 4.68; Value1: Unknown; U/M: EA; Value: 4700pF; TaMax_C: 125°C; SizeZ_mm: 1; SizeX_mm: 1.6; SizeY_mm: 0.8; Value2: 100V; SizeArea_mm2: 1.28; Cap_F: 4.7nF; AEC Category: Q200
C78 = CMP-0006979-5: CAP, CERM, 0.1 uF, 25 V, +/- 10%, X7R, 0603; Manufacturer: Kemet; TaMin_C: -55°C; Polarized: N; SizeAreaWB_mm2: 4.68; Value1: Unknown; U/M: EA; Value: 0.1uF; TaMax_C: 125°C; SizeZ_mm: 1; SizeX_mm: 1.6; SizeY_mm: 0.8; Value2: 25V; SizeArea_mm2: 1.28; AEC Category: Q200
FB7 FB8 = CMP-0092964-1: Chip Ferrite Bead, 0603, 1000Ω @ 100MHz, 0.5Ω, 25%, 450mA; Manufacturer: Murata; SizeZ_mm: 0.95mm; AEC Qualified: Yes; DCR_ohm: 0.5; AEC Grade: Grade 1
J16 = CMP-0074911-1: Terminal Block, 5.08 mm, 3x1, Brass, TH; Manufacturer: On-Shore Technology; Cert_VDE: Y; CNHeader: False; Current_A: 15A; Green_Lifecycle: Not Set; Shrouded: N; Gender: Female; Green_REACh: Incomplete; Voltage_V: 300V; Row_Count: 1; Pitch_mm: 5.08; CT: True
J17 = CMP-0055090-1: Header, 100mil, 8x1, TH; Manufacturer: Mill-Max; CT: FALSE; CNHeader: TRUE
J19 = CMP-0055713-1: Receptacle, 2.54mm, 2x2, Gold, TH; Manufacturer: Samtec; Current_A: 4.7A; Voltage_V: 465V; Row_Count: 2; CNHeader: FALSE; Gender: Female; CompType: Socket Strip; RowSpacing_mm: 2.54; CT: TRUE; Cert_UL: Y
R86 R89 = CMP-0025874-4: RES, 0, 5%, 0.1 W, AEC-Q200 Grade 0, 0603; Manufacturer: Panasonic; Power_W: 100mW; TempCo: 600 ppm/C; Value_Code: 0000; Value: 0; EIA_Code: E24; SizeX_mm: 1.6; SizeY_mm: 0.8; SizeZ_mm: 1; Value2: 0.1W; SizeArea_mm2: 1.28; AEC Qualified: Y; VDC_V: 50V; AEC Category: Q200; SizeAreaWB_mm2: 4.68
R87 R88 R90 R91 = CMP-0025787-4: RES, 33, 5%, 0.1 W, AEC-Q200 Grade 0, 0603; Manufacturer: Vishay-Dale; Power_W: 100mW; TempCo: 200 ppm/C; Value_Code: 33R0; Value: 33; EIA_Code: E24; SizeX_mm: 1.6; SizeY_mm: 0.8; SizeZ_mm: 1; Value2: 0.1W; SizeArea_mm2: 1.28; AEC Qualified: Y; VDC_V: 75V; AEC Category: Q200; AEC Grade: 0
R92 R94 R106 = CMP-0025885-5: RES, 0, 5%, 0.1 W, 0603; Manufacturer: Yageo; Power_W: 100mW; TempCo: 200 ppm/C; Value_Code: 0000; Value: 0; EIA_Code: E24; SizeX_mm: 1.6; SizeZ_mm: 1; Value2: 0.1W; SizeArea_mm2: 1.28; CompType: Resistor; AEC Qualified: N; VDC_V: 75V; AEC Category: Q200; SizeY_mm: 0.8; SizeAreaWB_mm2: 4.68
R93 R95 = CMP-0022448-4: RES, 49.9, 1%, 0.1 W, AEC-Q200 Grade 0, 0603; Manufacturer: Vishay-Dale; Power_W: 100mW; TempCo: 100 ppm/C; Value_Code: 49R9; Value: 49.9; EIA_Code: E96; SizeX_mm: 1.6; SizeY_mm: 0.8; SizeZ_mm: 1; Value2: 0.1W; SizeArea_mm2: 1.28; AEC Qualified: Y; VDC_V: 75V; AEC Category: Q200; AEC Grade: 0
R96-R98 = CMP-0025080-3: RES, 2.00 k, 0.5%, 0.1 W, 0603; Manufacturer: Yageo America; Power_W: 100mW; TempCo: 25 ppm/C; Value_Code: 2k00; U/M: EA; Value: 2.00k; EIA_Code: E192; Res_ohm: 2k; SizeX_mm: 1.6; SizeY_mm: 0.8; SizeZ_mm: 1; Value2: 0.1W; SizeArea_mm2: 1.28; CompType: Resistor; VDC_V: 75V; AEC Category: Q200
R99 = CMP-0021990-4: RES, 100 k, 1%, 0.1 W, AEC-Q200 Grade 0, 0603; Manufacturer: Vishay-Dale; Power_W: 100mW; TempCo: 100 ppm/C; Value: 100k; EIA_Code: E96; SizeX_mm: 1.6; SizeY_mm: 0.8; SizeZ_mm: 1; Value2: 0.1W; SizeArea_mm2: 1.28; AEC Qualified: Y; VDC_V: 75V; AEC Category: Q200; AEC Grade: 0
U7 = CMP-0093943-1: 3-Channel, Simultaneously-Sampling, 24-Bit, Reinforced Isolated DeltaSigma ADC With Integrated DC/DC Converter; Manufacturer: Texas Instruments; Interface: SPI; TaMax_C: +125°C; Standoff Height: 0.1mm; Resolution: 24bits; Max Supply Voltage: 5.5V; Data Polarity: Differential; Min Supply Voltage: 3V; TJmax_C: +150°C; Number Of Channels: 3; Sampling Rate: 32ksps; TaMin_C: -40°C; SizeZ_mm: 3.55mm; AEC Qualified: No
U8 = CMP-0092928-2: 3-Axis Linear Hall Effect Sensor With I2C Interface SOT23-6; Manufacturer: Texas Instruments; Standoff Height: 0mm; TaMin_C: -40°C; CompType: IC; AEC Qualified: No; Operating Supply Current: 2.3-2.7mA; Min Supply Voltage: 1.7V; SizeZ_mm: 1.45mm; Max Supply Voltage: 3.6V; AEC Category: Q200; TaMax_C: +125°C; TJmax_C: +150°C; AEC Grade: NA

## Sheet TIDA-010244_BLE_Module_HY-2340.SchDoc
size A4; Date: Not shown in title block; ApprovedBy: Not shown in title block; CheckedBy: Not shown in title block; Author: Not shown in title block; CompanyName: Not shown in title block; Engineer: Not shown in title block; Organization: Not shown in title block; Address1: Not shown in title block; Address2: Not shown in title block; Address3: Not shown in title block; Address4: Not shown in title block; DocumentNumber: 1; Revision: Use project parameter SCH_Rev; SheetNumber: 9; SheetTotal: 9; PageSetup: Record=PageOptions¦CenterHorizontal=True¦CenterVertical=True¦PrintScale=0.69¦XCorrection=1.00¦YCorrection=1.00¦PrintKind=0¦BorderSize=5000000¦LeftOffset=0¦BottomOffset=0¦Orientation=2¦PaperLength=1000¦PaperWidth=1000¦Scale=100¦PaperSource=15¦PrintQuality=600¦MediaType=1¦DitherType=10¦PaperKind=Letter¦PrintScaleMode=1
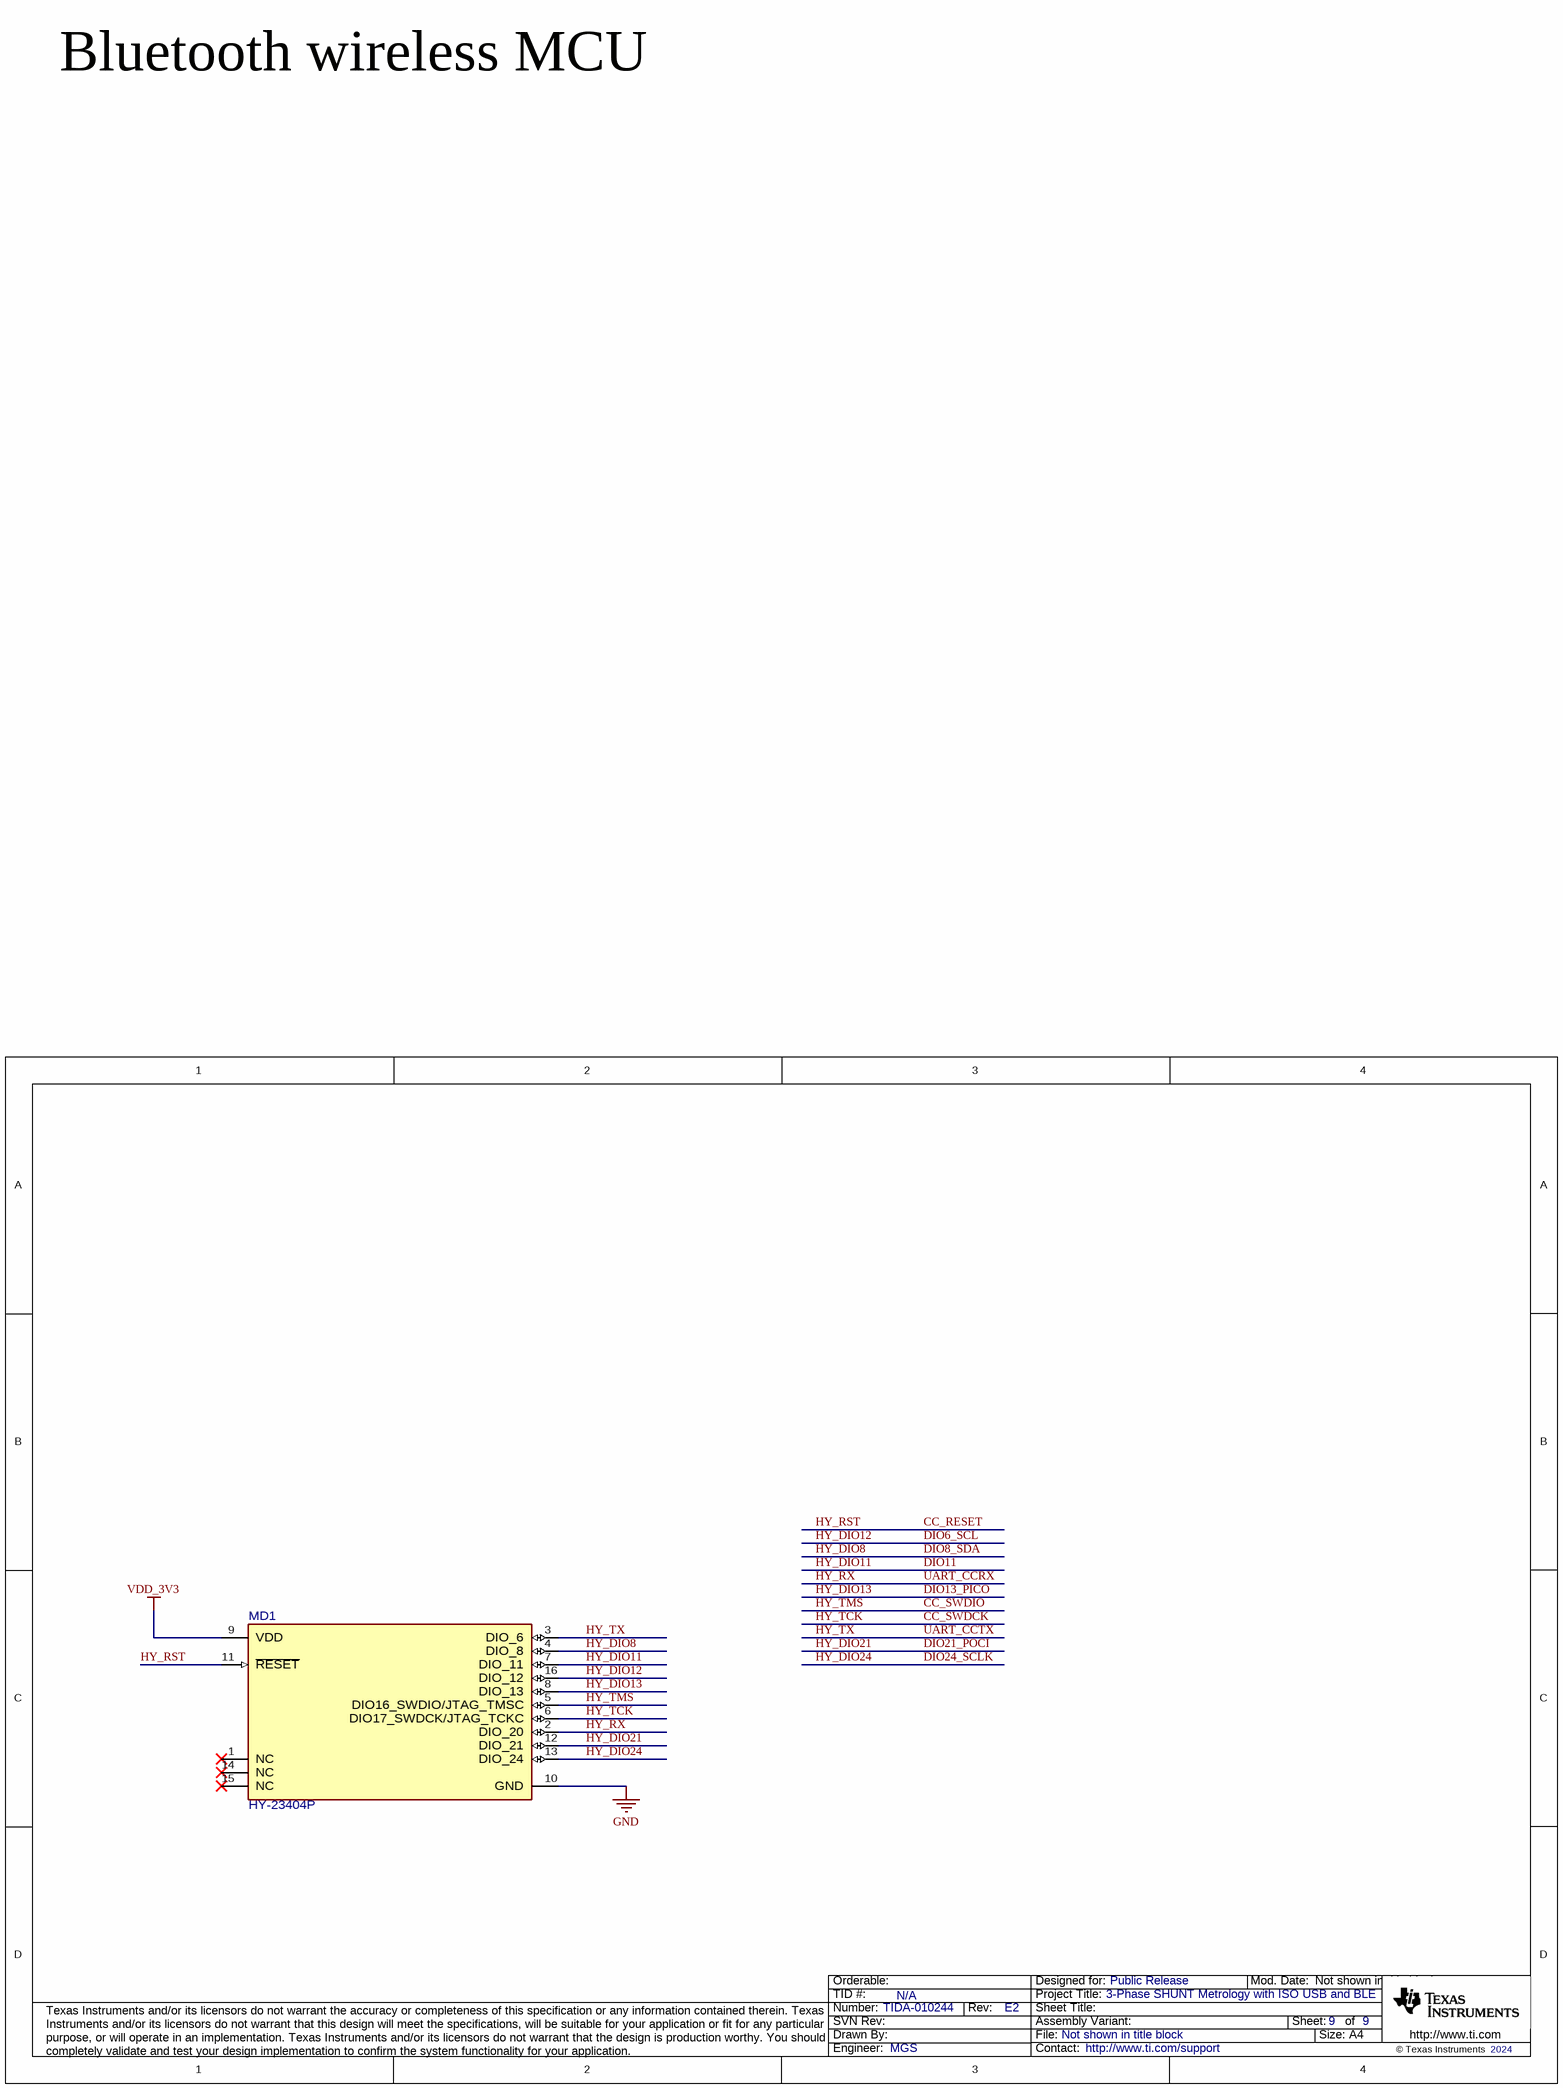
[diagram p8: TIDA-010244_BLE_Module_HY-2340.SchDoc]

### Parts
MD1  HY-23404P  [FP-HY-23404P_MD16-MFG]

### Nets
GND: MD1.10(GND)
VDD_3V3: MD1.9(VDD)
CC_RESET: MD1.11(~{RESET})  [also labelled HY_RST]
CC_SWDCK: MD1.6(DIO17_SWDCK/JTAG_TCKC)  [also labelled HY_TCK]
CC_SWDIO: MD1.5(DIO16_SWDIO/JTAG_TMSC)  [also labelled HY_TMS]
DIO6_SCL: MD1.16(DIO_12)  [also labelled HY_DIO12]
DIO8_SDA: MD1.4(DIO_8)  [also labelled HY_DIO8]
DIO11: MD1.7(DIO_11)  [also labelled HY_DIO11]
DIO13_PICO: MD1.8(DIO_13)  [also labelled HY_DIO13]
DIO21_POCI: MD1.12(DIO_21)  [also labelled HY_DIO21]
DIO24_SCLK: MD1.13(DIO_24)  [also labelled HY_DIO24]
HY_RX: MD1.2(DIO_20)  [also labelled UART_CCRX]
HY_TX: MD1.3(DIO_6)  [also labelled UART_CCTX]

Not connected (* = marked no-connect by the designer): MD1 1(NC)* 14(NC)* 15(NC)*

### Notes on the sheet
- Bluetooth wireless MCU

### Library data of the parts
MD1 = CMP-0123405-1: Bluetooth 5.3 Module Hardware; Manufacturer: Shenzhen Shengrun Technology; SizeZ_mm: 2.7mm; AEC Qualified: No; Bandwidth: 83.5MHz; Interface: I2C; Max Frequency: 2.4835GHz; Max Supply Voltage: 3.8V; Min Supply Voltage: 2.2V; Number Of Gpio: 10; Receiving Current: 5.3mA; Sensitivity: -93dBm; Transmitting Current: 12mA

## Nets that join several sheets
+3V3_XDS110: TIDA-010244_USB_and_Power (12 pins), TIDA-010244_XDS110_MCU (34 pins)
+5V0_XDS110: TIDA-010244_USB_and_Power (5 pins), TIDA-010244_XDS110_MCU (R117.1)
GND: TIDA-010244_3xISO_ADC_Rev2 (12 pins), TIDA-010244_MSPM0G_Rev2 (23 pins), TIDA-010244_V_I_Filtering_FE_Rev2 (J25.1 J25.2 J25.3 J25.4), TIDA-010244_USB_and_Power (22 pins), TIDA-010244_BLE_Wireless (28 pins), TIDA-010244_XDS110_MCU (36 pins), TIDA-010244_Neutral_3DHall_Rev2 (8 pins), TIDA-010244_BLE_Module_HY-2340 (MD1.10)
HGND_A_FB: TIDA-010244_3xISO_ADC_Rev2 (7 pins), TIDA-010244_V_I_Filtering_FE_Rev2 (5 pins)
HGND_B_FB: TIDA-010244_3xISO_ADC_Rev2 (7 pins), TIDA-010244_V_I_Filtering_FE_Rev2 (5 pins)
HGND_C_FB: TIDA-010244_3xISO_ADC_Rev2 (7 pins), TIDA-010244_V_I_Filtering_FE_Rev2 (5 pins)
HGND_D_FB: TIDA-010244_V_I_Filtering_FE_Rev2 (9 pins), TIDA-010244_Neutral_3DHall_Rev2 (12 pins)
VDD_3V3: TIDA-010244_3xISO_ADC_Rev2 (15 pins), TIDA-010244_MSPM0G_Rev2 (15 pins), TIDA-010244_V_I_Filtering_FE_Rev2 (J24.1 J24.2 J24.3 J24.4), TIDA-010244_USB_and_Power (10 pins), TIDA-010244_BLE_Wireless (14 pins), TIDA-010244_Neutral_3DHall_Rev2 (9 pins), TIDA-010244_BLE_Module_HY-2340 (MD1.9)
ADC_CLKIN_1: TIDA-010244_3xISO_ADC_Rev2 (R23.2), TIDA-010244_MSPM0G_Rev2 (R18.2)
ADC_CLKIN_2: TIDA-010244_3xISO_ADC_Rev2 (R32.2), TIDA-010244_MSPM0G_Rev2 (R21.2)
ADC_CLKIN_3: TIDA-010244_3xISO_ADC_Rev2 (R40.2), TIDA-010244_MSPM0G_Rev2 (R22.2)
ADC_CLKIN_4: TIDA-010244_MSPM0G_Rev2 (R20.2), TIDA-010244_Neutral_3DHall_Rev2 (R86.2)
ADC_CS1: TIDA-010244_3xISO_ADC_Rev2 (J4.1 R36.1 U4.19), TIDA-010244_MSPM0G_Rev2 (U1.26)
ADC_CS2: TIDA-010244_3xISO_ADC_Rev2 (J5.1 R39.1 U5.19), TIDA-010244_MSPM0G_Rev2 (U1.31)
ADC_CS3: TIDA-010244_3xISO_ADC_Rev2 (J6.1 R42.1 U6.19), TIDA-010244_MSPM0G_Rev2 (U1.47)
ADC_CS4: TIDA-010244_MSPM0G_Rev2 (U1.58), TIDA-010244_Neutral_3DHall_Rev2 (J17.2 R99.1 U7.19)
ADC_DIN_MSP_DOUT: TIDA-010244_3xISO_ADC_Rev2 (R29.2 R31.1 R37.2 R45.2), TIDA-010244_MSPM0G_Rev2 (U1.60), TIDA-010244_Neutral_3DHall_Rev2 (R90.2)
ADC_DOUT_MSP_DIN: TIDA-010244_3xISO_ADC_Rev2 (R25.1 R30.2 R38.2 R46.2), TIDA-010244_MSPM0G_Rev2 (U1.59), TIDA-010244_Neutral_3DHall_Rev2 (R91.2)
ADC_DRDY_1: TIDA-010244_3xISO_ADC_Rev2 (R26.2), TIDA-010244_MSPM0G_Rev2 (U1.19)
ADC_DRDY_2: TIDA-010244_3xISO_ADC_Rev2 (R33.2), TIDA-010244_MSPM0G_Rev2 (U1.23)
ADC_DRDY_3: TIDA-010244_3xISO_ADC_Rev2 (R41.2), TIDA-010244_MSPM0G_Rev2 (U1.51)
ADC_DRDY_4: TIDA-010244_MSPM0G_Rev2 (U1.53), TIDA-010244_Neutral_3DHall_Rev2 (R87.2)
ADC_SYNC_RESET: TIDA-010244_3xISO_ADC_Rev2 (R24.1 R27.2 R34.2 R43.2), TIDA-010244_MSPM0G_Rev2 (U1.52), TIDA-010244_Neutral_3DHall_Rev2 (R88.2)
CC_RESET: TIDA-010244_MSPM0G_Rev2 (C5.2 J2.1 R3.1 U1.38), TIDA-010244_BLE_Wireless (C116.2 R122.2 U14.13), TIDA-010244_BLE_Module_HY-2340 (MD1.11)
CC_SWDCK: TIDA-010244_BLE_Wireless (JP7.1 U14.8), TIDA-010244_BLE_Module_HY-2340 (MD1.6)
CC_SWDIO: TIDA-010244_BLE_Wireless (JP6.1 U14.7), TIDA-010244_BLE_Module_HY-2340 (MD1.5)
DIO6_SCL: TIDA-010244_BLE_Wireless (U14.19), TIDA-010244_BLE_Module_HY-2340 (MD1.16)
DIO8_SDA: TIDA-010244_BLE_Wireless (U14.3), TIDA-010244_BLE_Module_HY-2340 (MD1.4)
DIO11: TIDA-010244_BLE_Wireless (U14.4), TIDA-010244_BLE_Module_HY-2340 (MD1.7)
DIO13_PICO: TIDA-010244_BLE_Wireless (U14.6), TIDA-010244_BLE_Module_HY-2340 (MD1.8)
DIO21_POCI: TIDA-010244_BLE_Wireless (U14.10), TIDA-010244_BLE_Module_HY-2340 (MD1.12)
DIO24_SCLK: TIDA-010244_BLE_Wireless (U14.12), TIDA-010244_BLE_Module_HY-2340 (MD1.13)
HY_RX: TIDA-010244_BLE_Wireless (JP8.3 U14.5), TIDA-010244_BLE_Module_HY-2340 (MD1.2)
HY_TX: TIDA-010244_BLE_Wireless (JP9.3 U14.9), TIDA-010244_BLE_Module_HY-2340 (MD1.3)
I_Phase_A_N: TIDA-010244_3xISO_ADC_Rev2 (U4.10), TIDA-010244_V_I_Filtering_FE_Rev2 (C59.1 C60.1 R75.2)
I_Phase_A_P: TIDA-010244_3xISO_ADC_Rev2 (U4.9), TIDA-010244_V_I_Filtering_FE_Rev2 (C60.2 C61.2 R77.2)
I_Phase_B_N: TIDA-010244_3xISO_ADC_Rev2 (U5.10), TIDA-010244_V_I_Filtering_FE_Rev2 (C62.1 C63.1 R79.2)
I_Phase_B_P: TIDA-010244_3xISO_ADC_Rev2 (U5.9), TIDA-010244_V_I_Filtering_FE_Rev2 (C63.2 C64.2 R81.2)
I_Phase_C_N: TIDA-010244_3xISO_ADC_Rev2 (U6.10), TIDA-010244_V_I_Filtering_FE_Rev2 (C65.1 C66.1 R83.2)
I_Phase_C_P: TIDA-010244_3xISO_ADC_Rev2 (U6.9), TIDA-010244_V_I_Filtering_FE_Rev2 (C66.2 C67.2 R85.2)
MCU_RXD: TIDA-010244_MSPM0G_Rev2 (U1.55), TIDA-010244_BLE_Wireless (JP8.1), TIDA-010244_XDS110_MCU (J9.2)
MCU_TCK: TIDA-010244_BLE_Wireless (JP7.2), TIDA-010244_XDS110_MCU (J102.4 U18.35 U19.1)
MCU_TMS: TIDA-010244_BLE_Wireless (JP6.2), TIDA-010244_XDS110_MCU (J102.2 U18.36 U19.2)
MCU_TXD: TIDA-010244_MSPM0G_Rev2 (U1.54), TIDA-010244_BLE_Wireless (JP9.1), TIDA-010244_XDS110_MCU (J9.4)
SPI_CLK_1: TIDA-010244_3xISO_ADC_Rev2 (R28.2), TIDA-010244_MSPM0G_Rev2 (R12.2)
SPI_CLK_2: TIDA-010244_3xISO_ADC_Rev2 (R35.2), TIDA-010244_MSPM0G_Rev2 (R15.2)
SPI_CLK_3: TIDA-010244_3xISO_ADC_Rev2 (R44.2), TIDA-010244_MSPM0G_Rev2 (R17.2)
SPI_CLK_4: TIDA-010244_MSPM0G_Rev2 (R13.2), TIDA-010244_Neutral_3DHall_Rev2 (R89.2)
SWCLK: TIDA-010244_MSPM0G_Rev2 (U1.13), TIDA-010244_BLE_Wireless (JP7.3)
SWDIO: TIDA-010244_MSPM0G_Rev2 (U1.12), TIDA-010244_BLE_Wireless (JP6.3)
TMAG_INT: TIDA-010244_MSPM0G_Rev2 (U1.35), TIDA-010244_Neutral_3DHall_Rev2 (R98.1 U8.5)
TMAG_SCL: TIDA-010244_MSPM0G_Rev2 (U1.36), TIDA-010244_Neutral_3DHall_Rev2 (R96.1 U8.1)
TMAG_SDA: TIDA-010244_MSPM0G_Rev2 (U1.37), TIDA-010244_Neutral_3DHall_Rev2 (R97.1 U8.6)
UART_RX_to_BLE: TIDA-010244_MSPM0G_Rev2 (U1.15), TIDA-010244_BLE_Wireless (JP9.2)
UART_TX_to_BLE: TIDA-010244_MSPM0G_Rev2 (U1.14), TIDA-010244_BLE_Wireless (JP8.2)
V_Phase_A_N: TIDA-010244_3xISO_ADC_Rev2 (U4.7), TIDA-010244_V_I_Filtering_FE_Rev2 (C50.1 C51.1 R56.2)
V_Phase_A_P: TIDA-010244_3xISO_ADC_Rev2 (U4.8), TIDA-010244_V_I_Filtering_FE_Rev2 (C51.2 C52.2 R61.2)
V_Phase_B_N: TIDA-010244_3xISO_ADC_Rev2 (U5.7), TIDA-010244_V_I_Filtering_FE_Rev2 (C53.1 C54.1 R62.2)
V_Phase_B_P: TIDA-010244_3xISO_ADC_Rev2 (U5.8), TIDA-010244_V_I_Filtering_FE_Rev2 (C54.2 C55.2 R67.2)
V_Phase_C_N: TIDA-010244_3xISO_ADC_Rev2 (U6.7), TIDA-010244_V_I_Filtering_FE_Rev2 (C56.1 C57.1 R68.2)
V_Phase_C_P: TIDA-010244_3xISO_ADC_Rev2 (U6.8), TIDA-010244_V_I_Filtering_FE_Rev2 (C57.2 C58.2 R73.2)
XDS_DM: TIDA-010244_USB_and_Power (R51.2), TIDA-010244_XDS110_MCU (U18.93)
XDS_DP: TIDA-010244_USB_and_Power (R53.2), TIDA-010244_XDS110_MCU (U18.94)
XDS_RESET_OUT: TIDA-010244_MSPM0G_Rev2 (J2.2), TIDA-010244_XDS110_MCU (J102.10 R118.1 U18.40 U20.1)

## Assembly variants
001: not fitted ANT1 C4 C11 C47 C78 C81 C101 C102 C103 C104 C105 C106 C107 C108 C110 C111 C112 C113 C114 C115 C116 C117 C118 C119 D6 FID1 FID2 FID3 J8 J19 J20 J21 J22 J23 J? JP1 L3 L4 L5 MD1 R8 R9 R10 R19 R48 R96 R97 R98 R122 R123 R124 R125 R127 TP4 TP8 U8 U14 U15 U16 U17 Y3 Y4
